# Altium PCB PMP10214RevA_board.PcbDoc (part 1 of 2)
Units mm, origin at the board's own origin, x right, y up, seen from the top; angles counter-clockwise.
Board outline 108.2 x 92.71 mm, 6 copper layers (Top Layer, MidLayer1, MidLayer2, MidLayer3, MidLayer4, Bottom Layer), stack 1.557 mm thick; 122 components, 44 nets, 289 pads, 1298 vias.
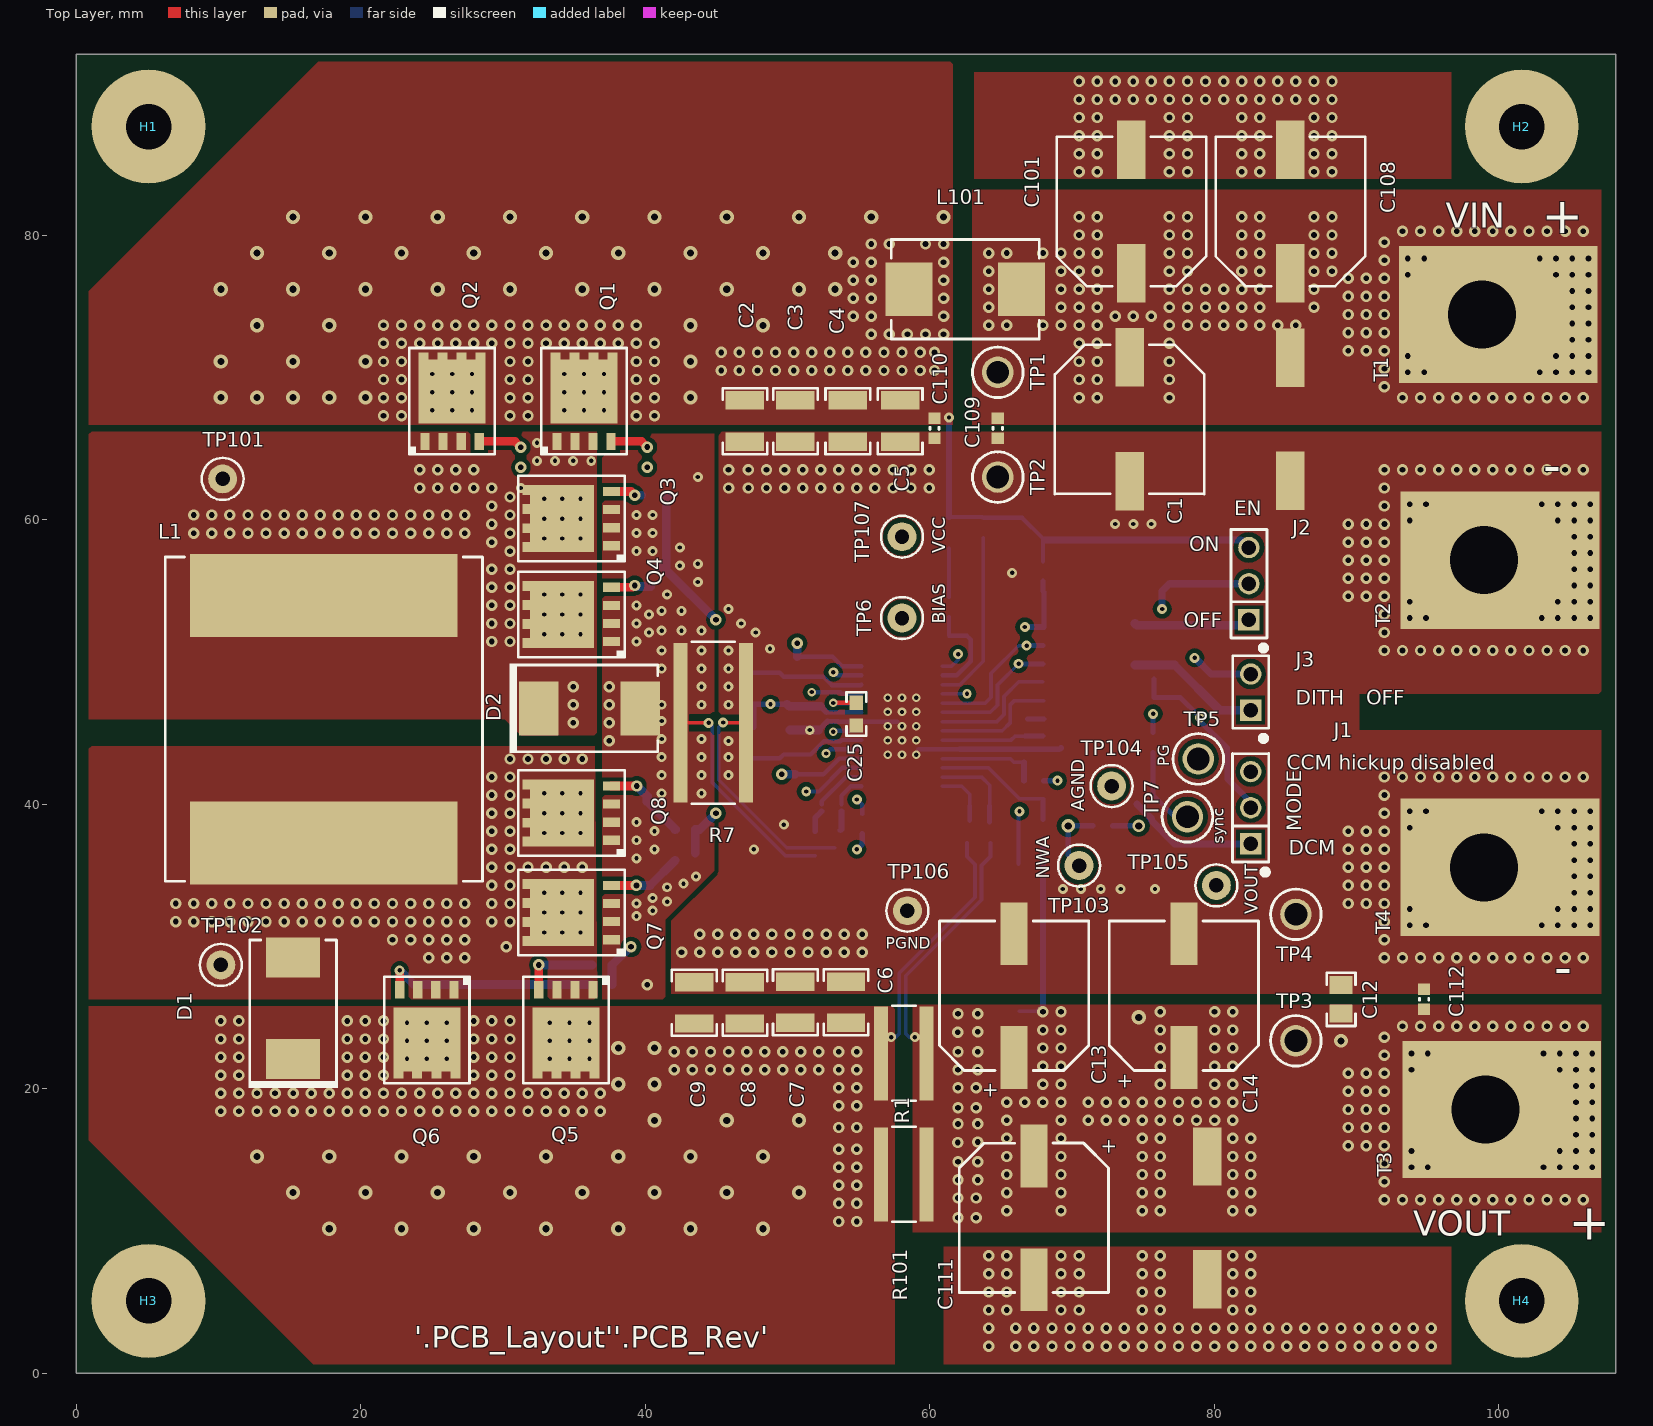
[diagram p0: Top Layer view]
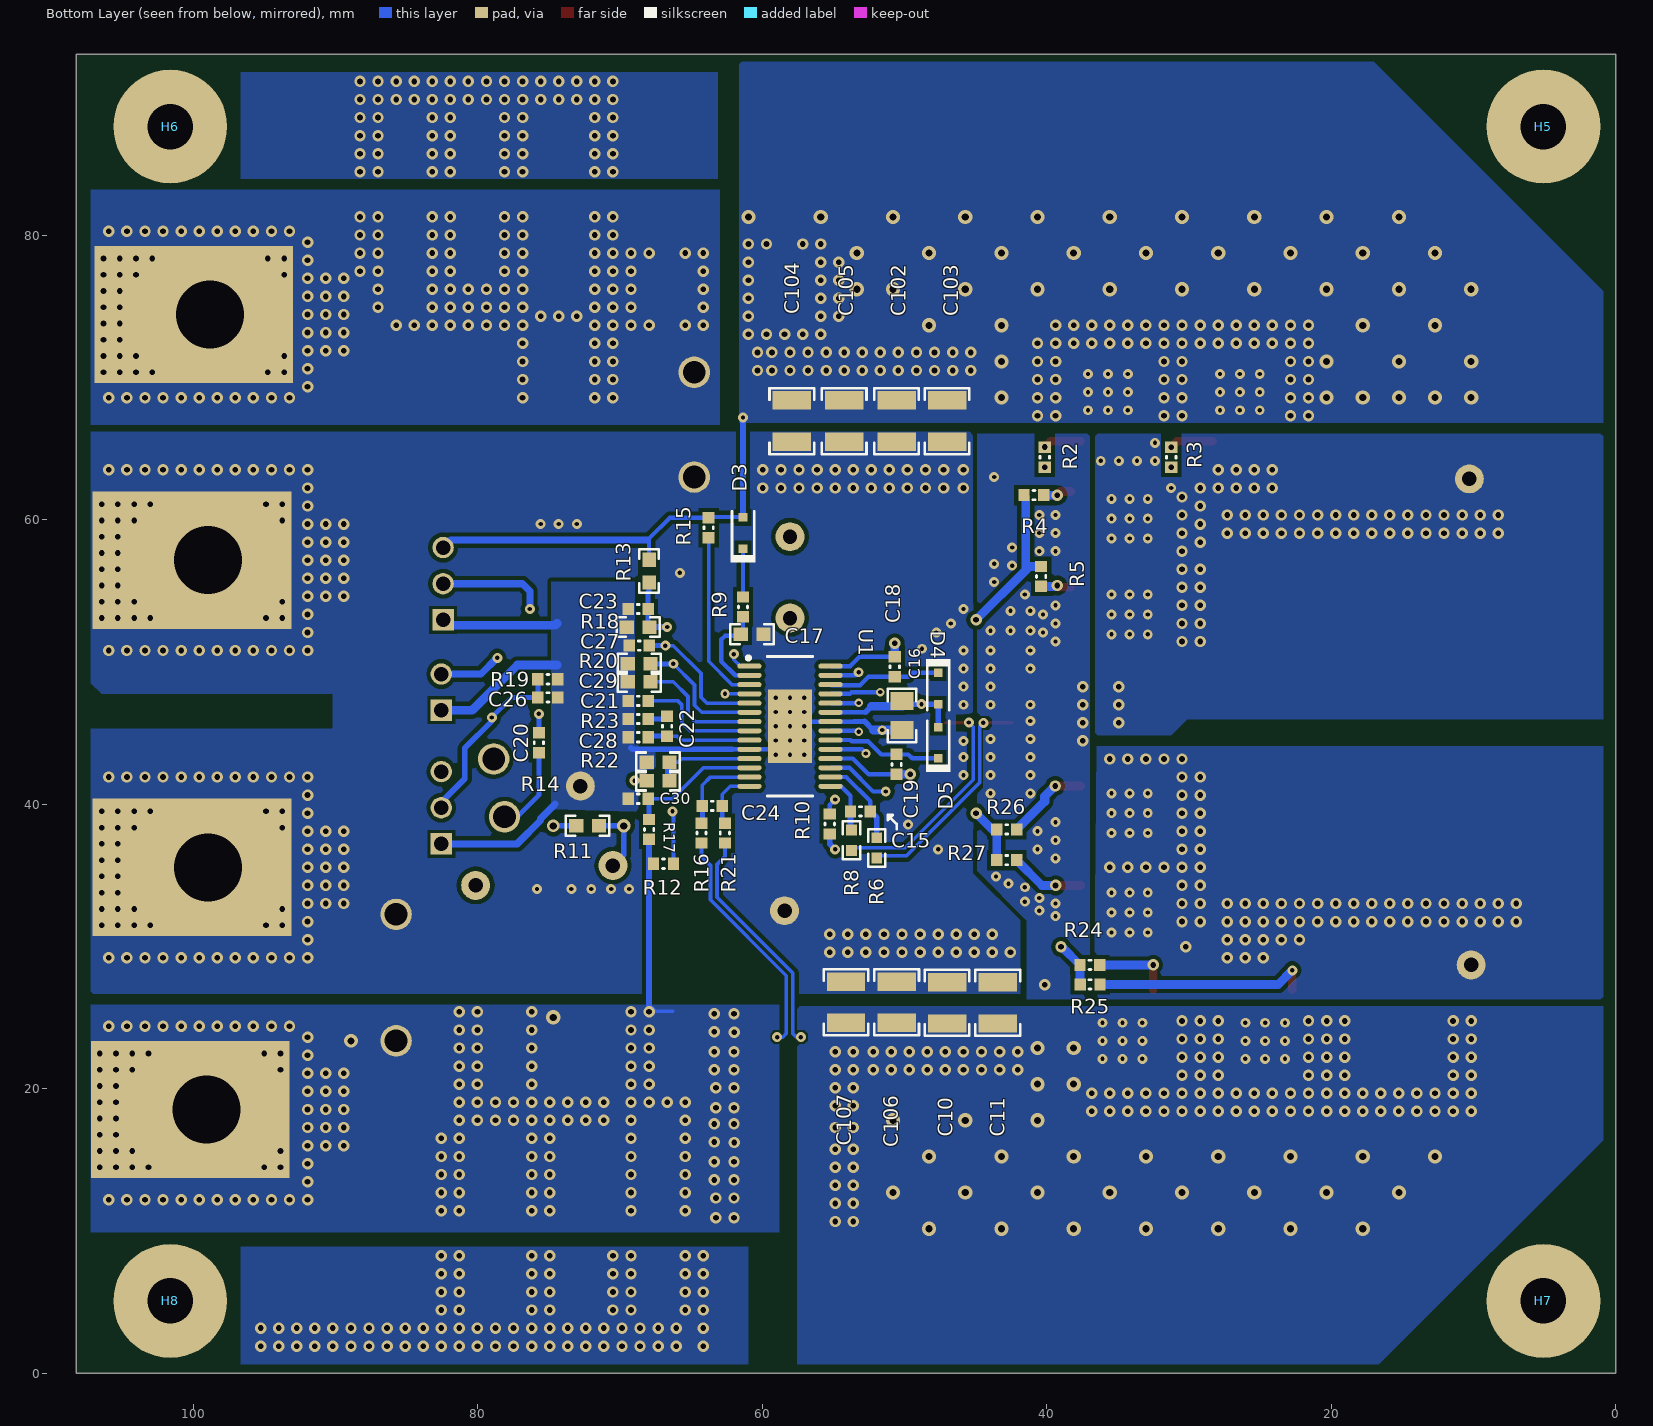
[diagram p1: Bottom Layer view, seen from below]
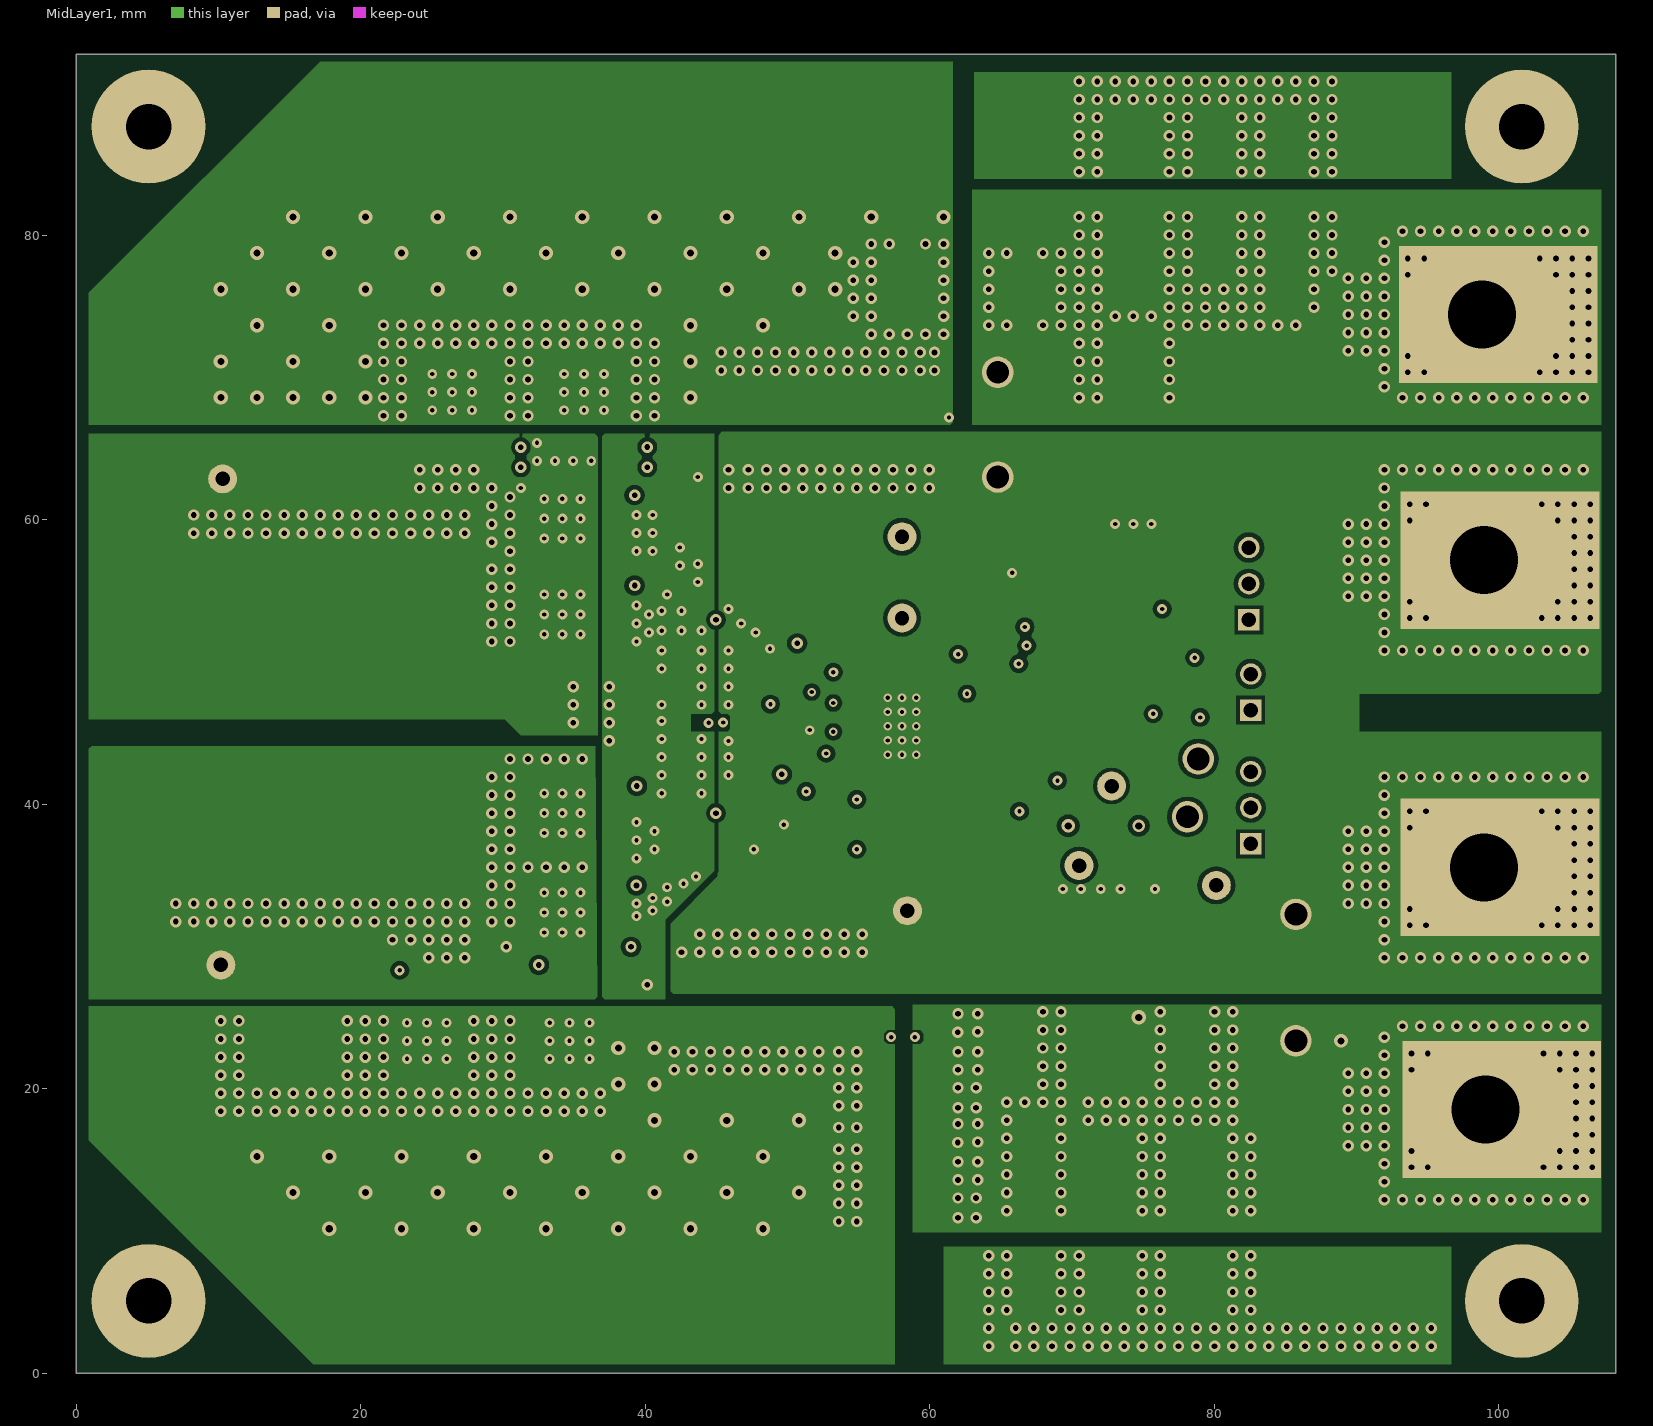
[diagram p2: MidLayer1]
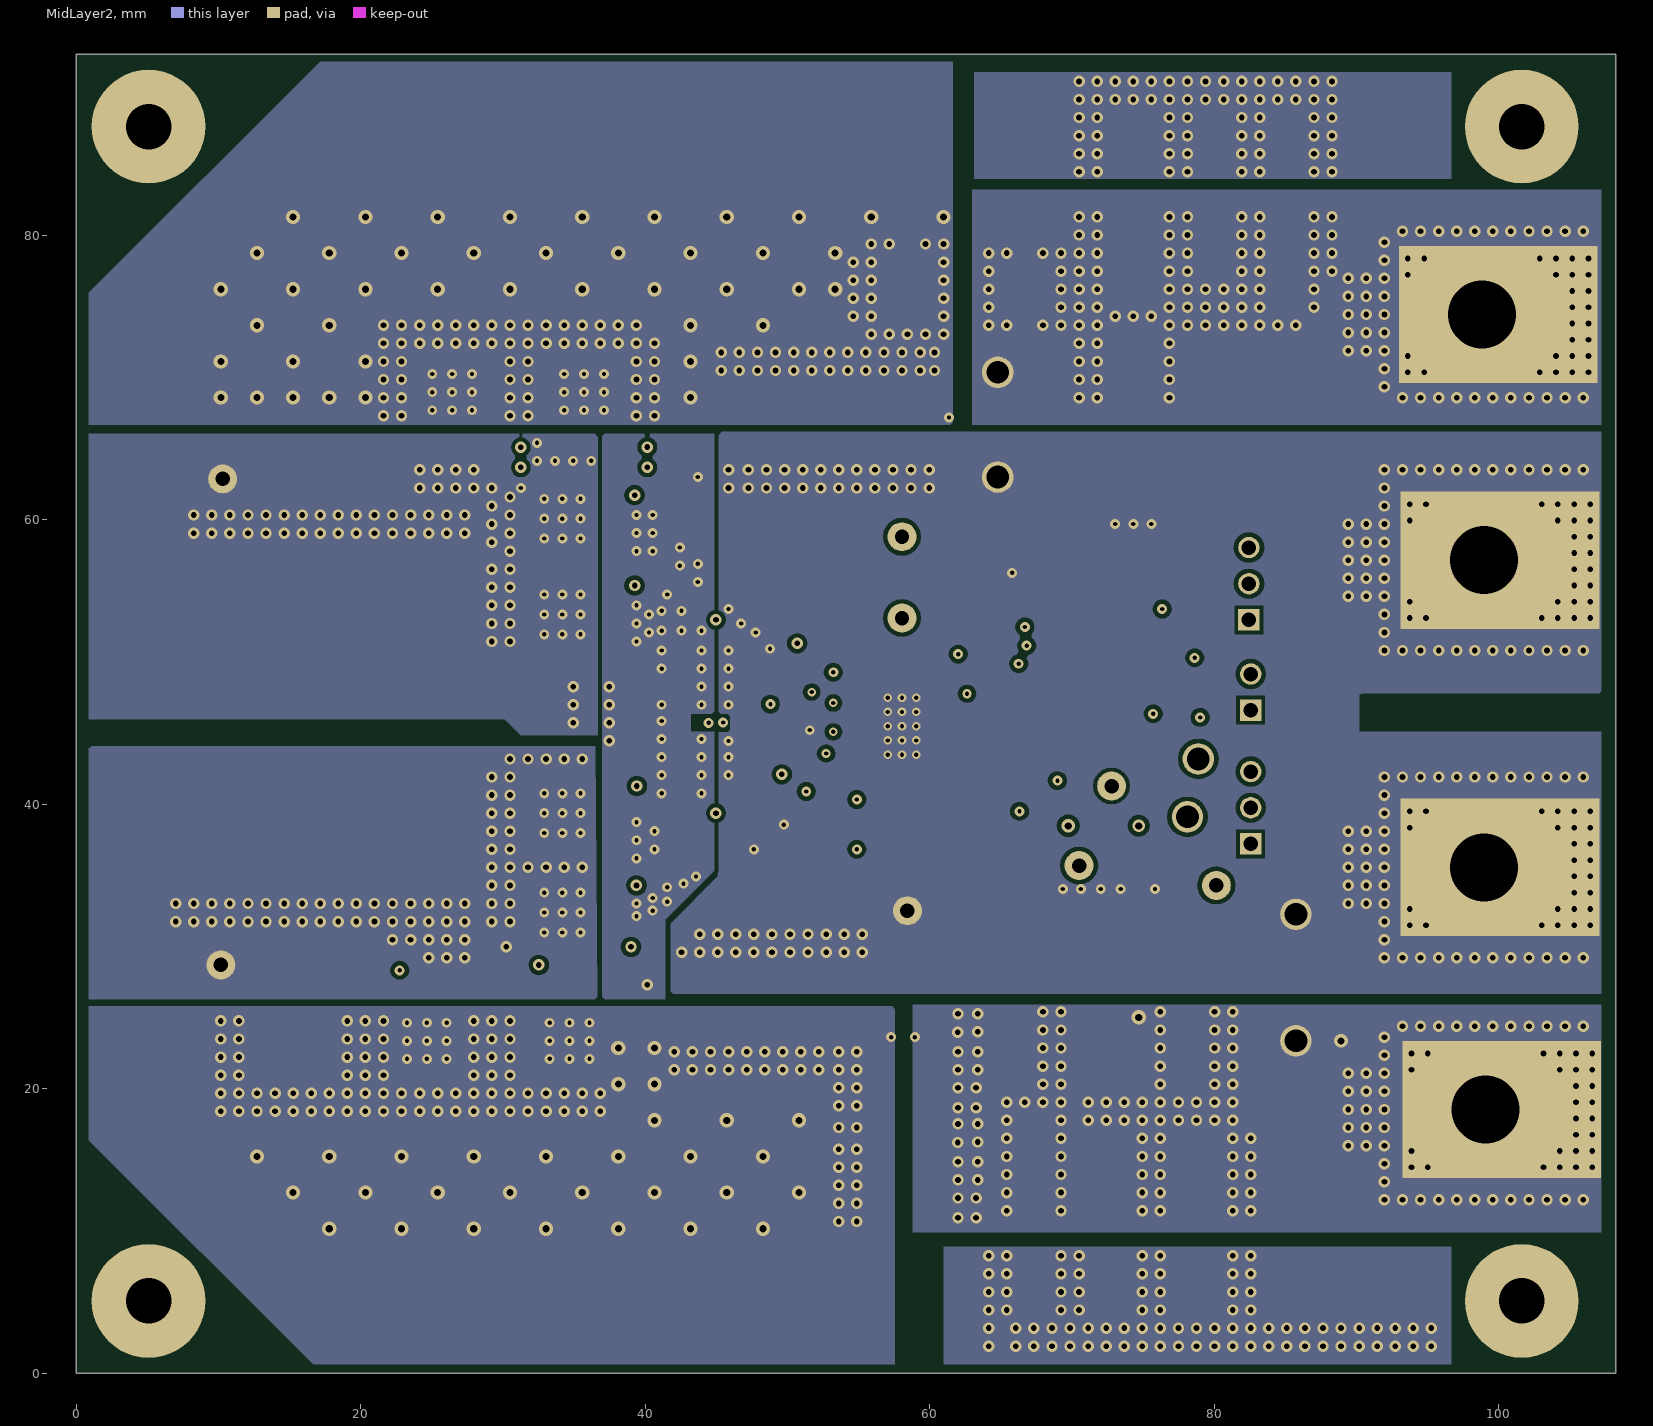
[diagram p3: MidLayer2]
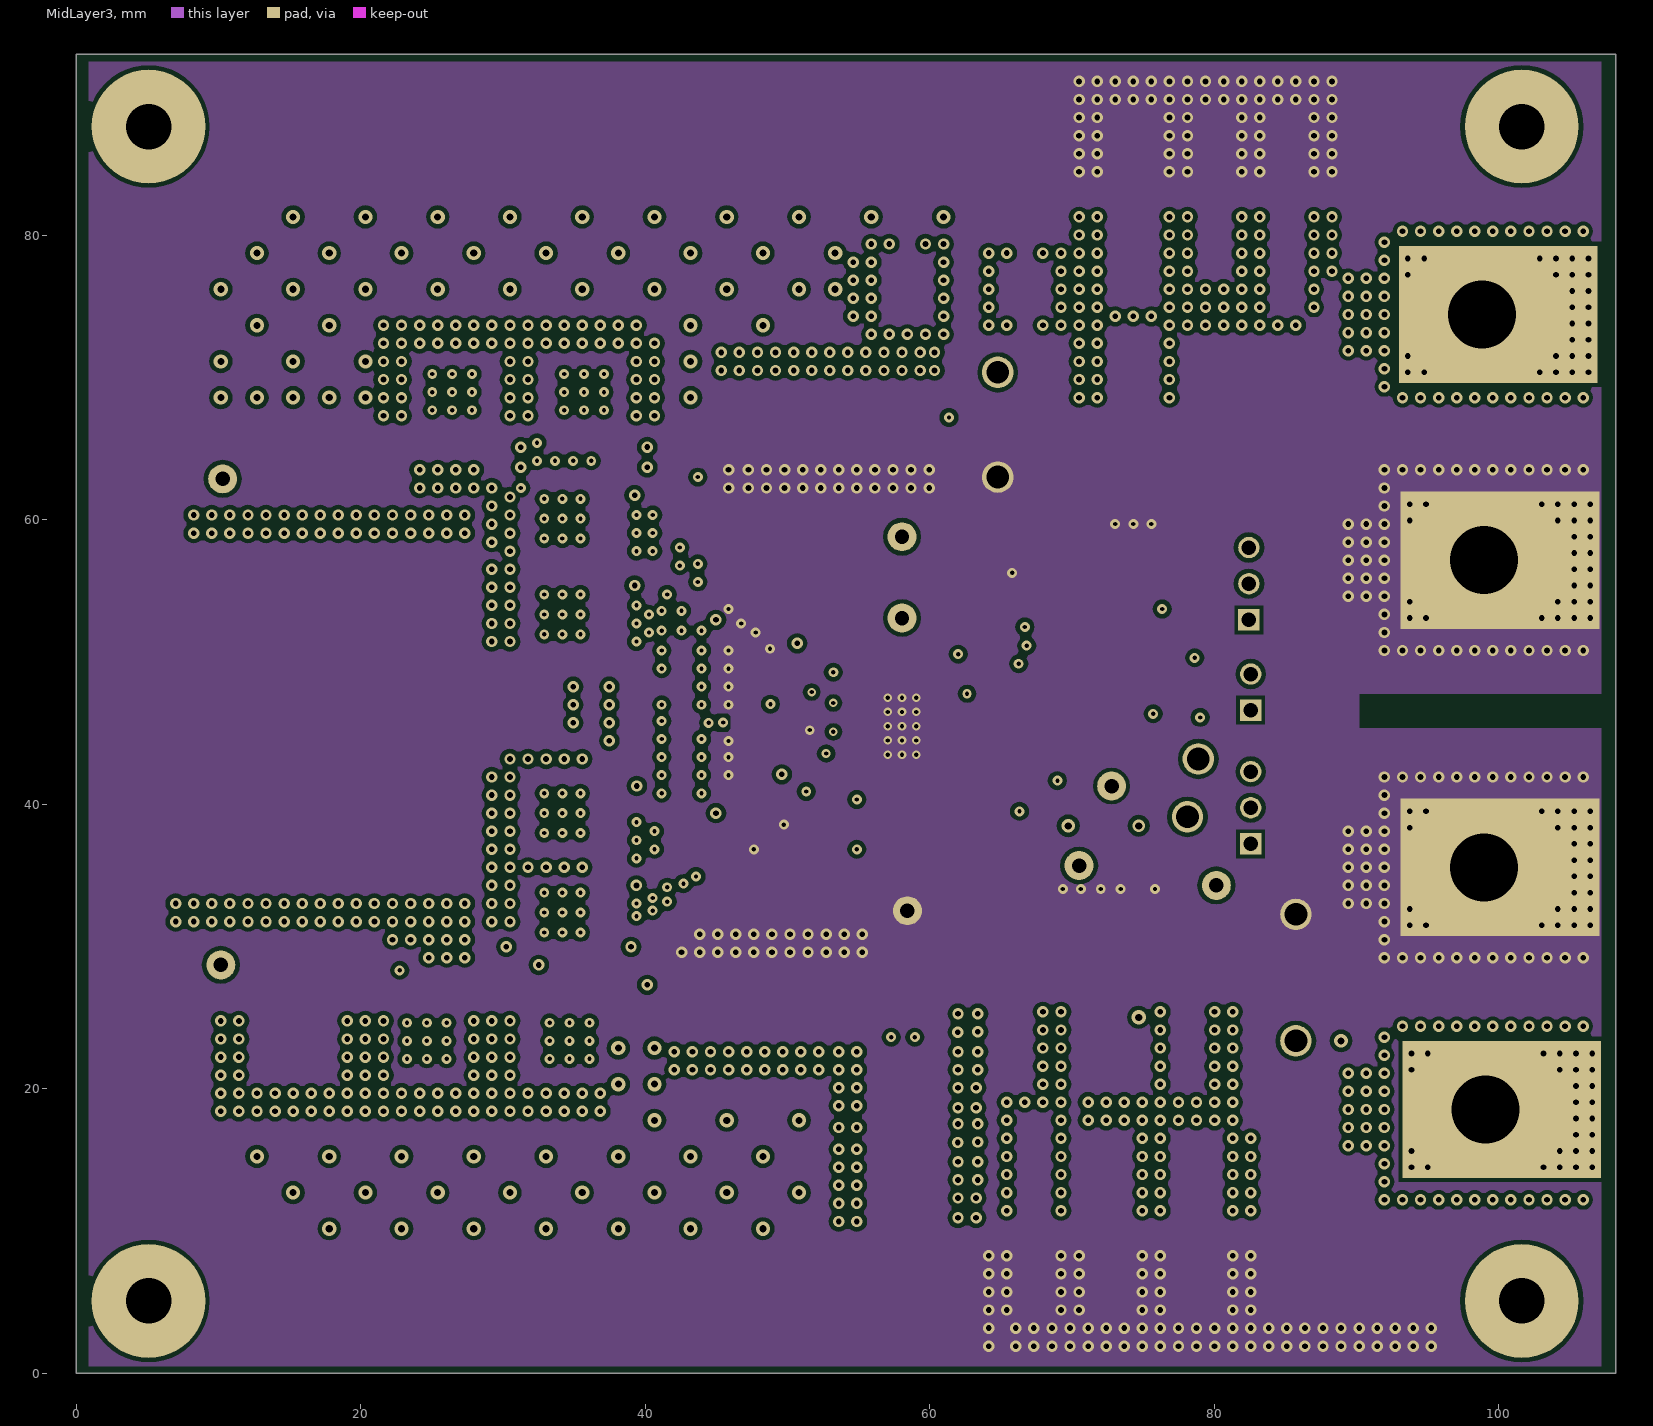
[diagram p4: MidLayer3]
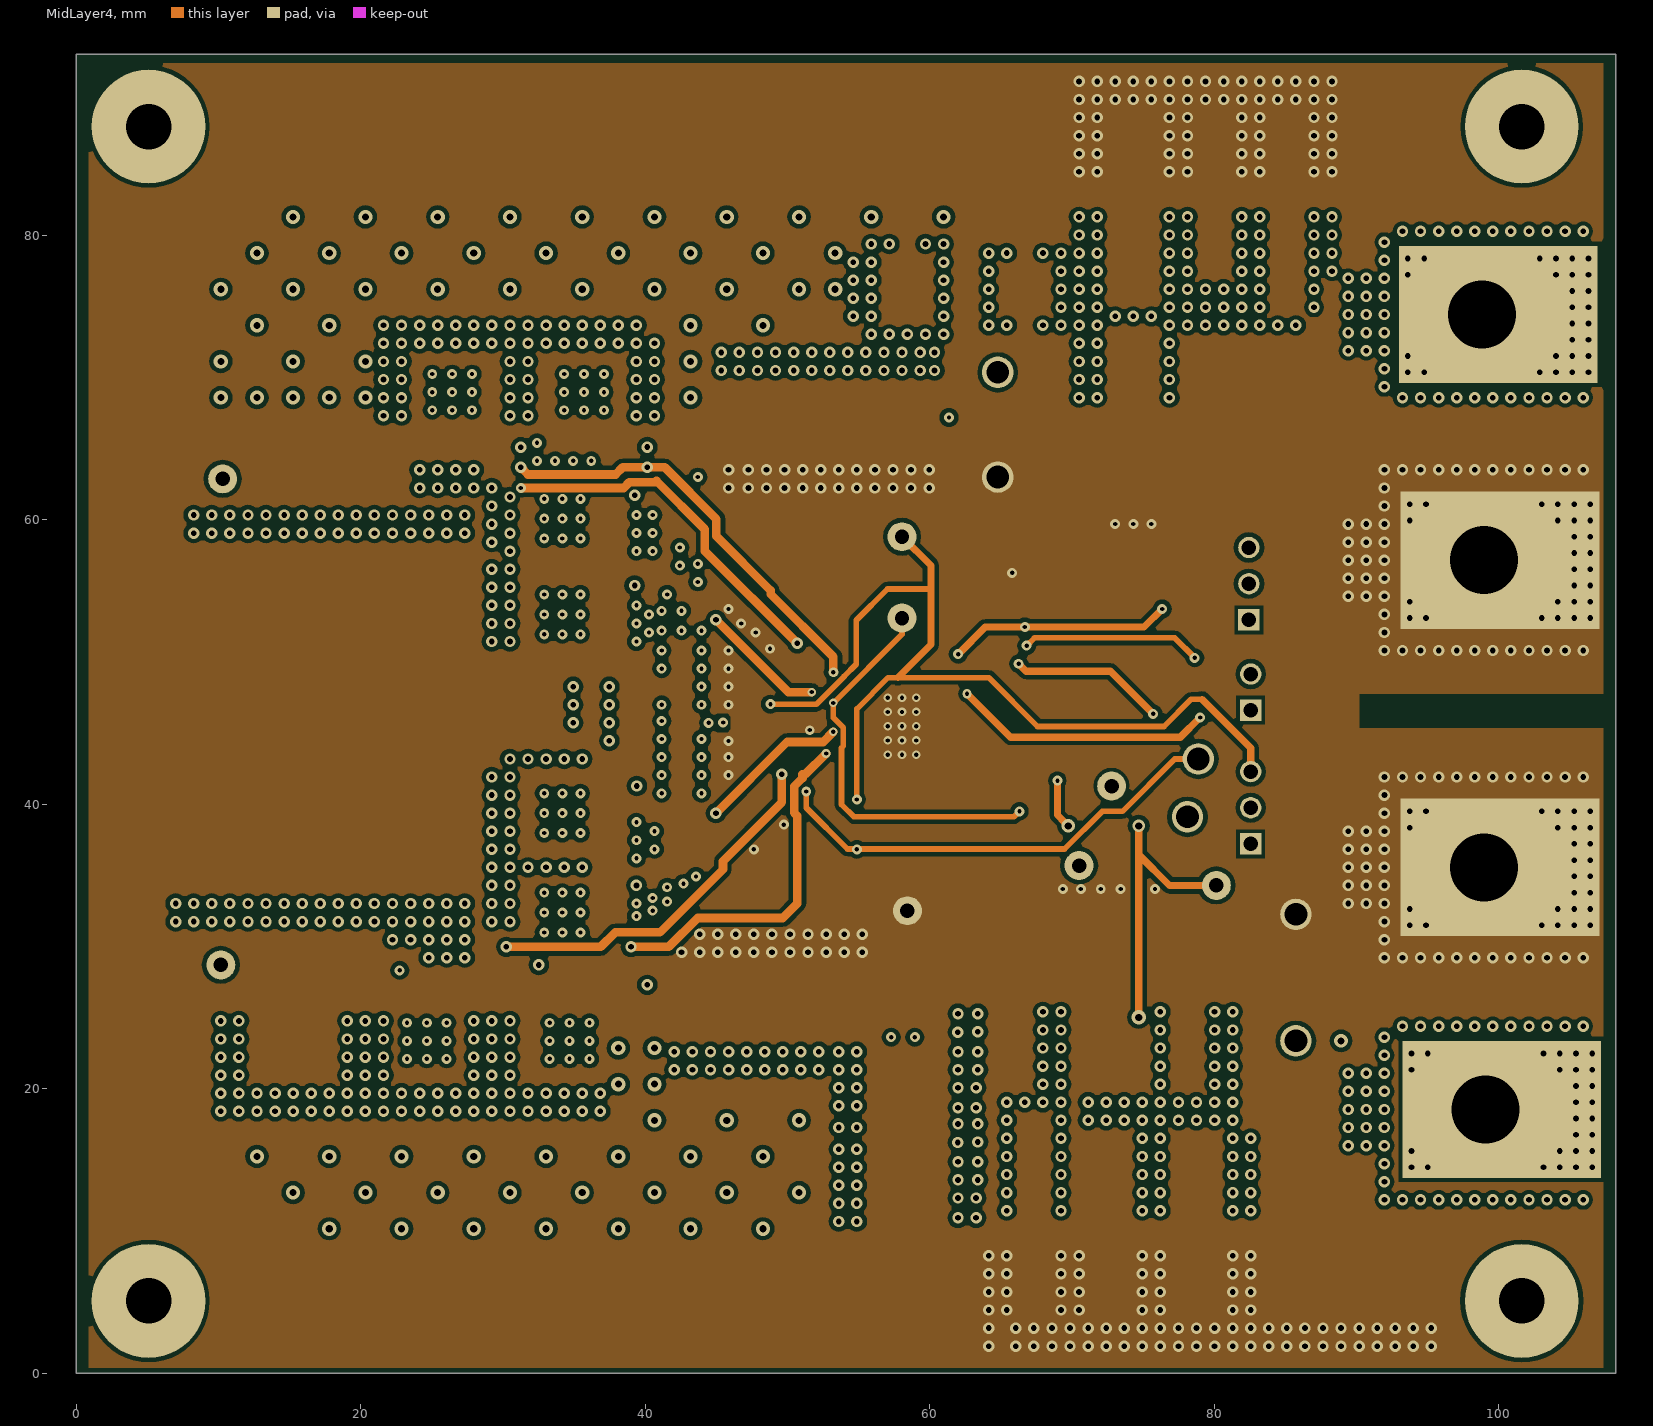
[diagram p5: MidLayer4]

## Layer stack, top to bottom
Top Solder: solder mask 0.0102, Solder Resist, Dk 3.5
Top Layer: signal copper 0.0711
Dielectric1: prepreg 0.2261, FR-4, Dk 4.2
MidLayer1: signal copper 0.0711
Dielectric3: prepreg 0.2261, FR-4, Dk 4.2
MidLayer2: signal copper 0.0711
Dielectric5: core 0.2261, FR-4, Dk 4.8
MidLayer3: signal copper 0.0711
Dielectric2: prepreg 0.2261, FR-4, Dk 4.8
MidLayer4: signal copper 0.0711
Dielectric4: prepreg 0.2261, FR-4, Dk 4.8
Bottom Layer: signal copper 0.0711
Bottom Solder: solder mask 0.0102, Solder Resist, Dk 3.5

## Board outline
0,0 0,92.71 108.204,92.71 108.204,0

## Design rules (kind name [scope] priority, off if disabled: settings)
AcuteAngle [All] p1: minimum=4.50000000000000E+0001 checktracksonly=FALSE
AssemblyTestPointUsage [All] p1: valid=2
Clearance Clearance_BoardEdge_MountingHoles [OnCopper and InComponentClass('Mounting Holes') vs KeepOut] p1: gap=1.016 ignorepadtopadclearanceinfootprint=FALSE except(0: Arc-Hole Track-Hole SMDPad-Hole THPad-Hole Via-Hole Fill-Hole Poly-Hole Region-Hole Text-Hole)
Clearance Clearance_BoardEdge_Poly [OnCopper and InPoly vs KeepOut] p2: gap=0.635 ignorepadtopadclearanceinfootprint=FALSE except(0: Arc-Hole Track-Hole SMDPad-Hole THPad-Hole Via-Hole Fill-Hole Poly-Hole Region-Hole Text-Hole)
Clearance Clearance_BoardEdge [OnCopper and Not InComponentClass('Logo') and not InComponentClass('FiducialMark') and not InRegion(1000,500,4000,800) and Not IsKeepout vs KeepOut] p3: gap=1.194 ignorepadtopadclearanceinfootprint=FALSE except(0: Arc-Hole Track-Hole SMDPad-Hole THPad-Hole Via-Hole Fill-Hole Poly-Hole Region-Hole Text-Hole)
Clearance Clearance_Poly [InPolygon] p4: gap=0.305 ignorepadtopadclearanceinfootprint=FALSE except(0: Arc-Hole Track-Hole SMDPad-Hole THPad-Hole Via-Hole Fill-Hole Poly-Hole Region-Hole Text-Hole)
Clearance [All] p5: gap=0.2 ignorepadtopadclearanceinfootprint=FALSE except(0: Arc-Hole Track-Hole SMDPad-Hole THPad-Hole Via-Hole Fill-Hole Poly-Hole Region-Hole Text-Hole)
ComponentClearance ComponentClearance_Shunt [InComponentClass('Header') vs InComponentClass('Shunt')] p1: gap=0 collisioncheckmode=3 verticalgap=0 showdistances=FALSE
ComponentClearance ComponentClearance_MountingHoles_FiducialMarks [InComponentClass('Mounting Holes') vs InComponentClass('FiducialMark')] p2: gap=1.067 collisioncheckmode=3 verticalgap=0.254 showdistances=FALSE
ComponentClearance ComponentClearance_Logo [InComponentClass('Logo')] p3: gap=1.27 collisioncheckmode=3 verticalgap=0.254 showdistances=FALSE
ComponentClearance ComponentClearance_ScrewToNut [(HasFootprint('NY PMS 440 0025 PH')) vs (HasFootprint('Keystone_1902C'))] p4: gap=0.127 collisioncheckmode=3 verticalgap=0.254 showdistances=FALSE
ComponentClearance ComponentClearance_MountingHoles [InComponentClass('Mounting Holes')] p5: gap=5.08 collisioncheckmode=3 verticalgap=2540 showdistances=FALSE
ComponentClearance ComponentClearance_SmallPassives [HasFootprint('0201*') or HasFootprint('0402*') or HasFootprint('0508') or HasFootprint('0603*') or HasFootprint('0612') or HasFootprint('0805*') or HasFootprint('0815*') or HasFootprint('0830*') or HasFootprint('1206*') or HasFootprint('1210*') or HasFootprint('1808*') or HasFootprint('1812*') or HasFootprint('1825*') or HasFootprint('2010*') or HasFootprint('2220*') or HasFootprint('2225*') or HasFootprint('2512*') or HasFootprint('2728*') or HasFootprint('3518*') vs HasFootprint('0201*') or HasFootprint('0402*') or HasFootprint('0508') or HasFootprint('0603*') or HasFootprint('0612') or HasFootprint('0805*') or HasFootprint('0815*') or HasFootprint('0830*') or HasFootprint('1206*') or HasFootprint('1210*') or HasFootprint('1808*') or HasFootprint('1812*') or HasFootprint('1825*') or HasFootprint('2010*') or HasFootprint('2220*') or HasFootprint('2225*') or HasFootprint('2512*') or HasFootprint('2728*') or HasFootprint('3518*')] p6: gap=0.254 collisioncheckmode=3 verticalgap=0.254 showdistances=FALSE
ComponentClearance ComponentClearance_THtoSMT [IsThruComponent vs IsSMTComponent] p7: gap=0.6 collisioncheckmode=3 verticalgap=0.762 showdistances=FALSE
ComponentClearance ComponentClearance_THtoTH [IsThruComponent vs IsThruComponent] p8: gap=0.635 collisioncheckmode=3 verticalgap=0.381 showdistances=FALSE
ComponentClearance [All] p9: gap=0.6 collisioncheckmode=3 verticalgap=0.254 showdistances=FALSE
DiffPairsRouting [All] p1: maxlimit=2.54 minlimit=0.254 mostfreqgap=0.254 toplayer_minwidth=0.381 toplayer_maxwidth=0.381 toplayer_prefwidth=0.381 midlayer1_minwidth=0.381 midlayer1_maxwidth=0.381 midlayer1_prefwidth=0.381 midlayer2_minwidth=0.381 midlayer2_maxwidth=0.381 midlayer2_prefwidth=0.381 midlayer3_minwidth=0.381 midlayer3_maxwidth=0.381 midlayer3_prefwidth=0.381 midlayer4_minwidth=0.381 midlayer4_maxwidth=0.381 midlayer4_prefwidth=0.381 bottomlayer_minwidth=0.381 bottomlayer_maxwidth=0.381 bottomlayer_prefwidth=0.381 maxuncoupledlength=25.4
FabricationTestPointUsage TestPointUsage [All] p1: valid=2 allowmultiple=FALSE
FabricationTestpoint Testpoint [All] p1: side=3 testpointundercomponent=TRUE minsize=1.016 maxsize=2.54 preferedsize=1.524 minholesize=0 maxholesize=1.016 preferedholesize=0.813 testpointgrid=0.025 allowsidetop=TRUE allowsidebottom=TRUE usegrid=TRUE gridtolerance=0
FanoutControl Fanout_LCC [IsLCC] p1: bgadir=Out bgaviamode=Centered fanoutstyle=Auto fanoutdirection=Alternating viagrid=0.025 // Fanout_LCC (Default Rule)
FanoutControl Fanout_BGA [IsBGA] p2: bgadir=Out bgaviamode=Centered fanoutstyle=Auto fanoutdirection=Alternating viagrid=0.025 // Fanout_BGA (Default Rule)
FanoutControl Fanout_Default [All] p4: bgadir=Out bgaviamode=Centered fanoutstyle=Auto fanoutdirection=Alternating viagrid=0.025 // Fanout_Default (Default Rule)
FanoutControl Fanout_Small [(CompPinCount < 5)] p5: bgadir=Out bgaviamode=Centered fanoutstyle=Auto fanoutdirection=OutThenIn viagrid=0.025 // Fanout_Small (Default Rule)
HoleSize [All] p1: absolutevalues=TRUE maxlimit=7.112 minlimit=0.3 maxpercent=80.000 minpercent=20.000
MinimumAnnularRing MinimumAnnularRing_ThermalPadVias [IsVia and InAnyComponent] p1: minimumring=0.1
MinimumAnnularRing [All] p2: minimumring=0.127
MinimumSolderMaskSliver MinimumSolderMaskSliver_Logo [InComponentClass('Logo') vs InComponentClass('Logo')] p1: minsoldermaskwidth=0.018
MinimumSolderMaskSliver [All] p2: minsoldermaskwidth=0.1
PlaneConnect [All] p1: planeconnectstyle=Relief reliefexpansion=0.254 reliefentries=4 reliefconductorwidth=0.254 reliefairgap=0.254
PolygonConnect [InComponent('J1') Or InComponent('J2') Or InComponent('J3')] p1: connectstyle=NoConnect reliefconductorwidth=0.254 reliefentries=4 polygonreliefangle="90 Angle" airgapwidth=0.254
PolygonConnect PolygonConnect_2 [OnLayer('Top Layer')Or OnLayer('MidLayer1') Or OnLayer('MidLayer2')Or OnLayer('MidLayer3')Or  OnLayer('MidLayer4') vs InComponent('TP104')] p2: connectstyle=NoConnect reliefconductorwidth=0.254 reliefentries=4 polygonreliefangle="90 Angle" airgapwidth=0.254
PolygonConnect PolygonConnect_1 [All] p3: connectstyle=Direct reliefconductorwidth=0.254 reliefentries=4 polygonreliefangle="90 Angle" airgapwidth=0.254
RoutingVias ThermalPadVias [IsVia and InAnyComponent] p1: holewidth=0.5 width=0.9 viastyle="Through Hole" minholewidth=0.3 minwidth=0.6 maxholewidth=1 maxwidth=2
RoutingVias [All] p2: holewidth=0.5 width=0.9 viastyle="Through Hole" minholewidth=0.3 minwidth=0.6 maxholewidth=1.016 maxwidth=1.651
SMDToCorner [All] p1: distance=30000
SilkToSilkClearance [All] p1: silktosilkclearance=0.127
SilkToSolderMaskClearance SilkscreenOverComponentPads [IsPad] p1: minsilkscreentomaskgap=0.127 clearancetoexposedcopper=TRUE
SolderMaskExpansion [All] p1: expansion=0.05 istentingtop=FALSE
Width [All] p1: maxlimit=2.54 minlimit=0.152 preferedwidth=0.254 checkconnectedcopper=TRUE
16 further rules are at their usual default settings.

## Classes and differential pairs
component class Header: J1 J2 J3
component class "Mounting Holes": H1 H2 H3 H4
component class PMP10214RevA-HW: H1 H2 H3 H4 H5 H6 H7 H8 ZZ2 ZZ3 ZZ4 ZZ5 ZZ6 ZZ7 ZZ8
component class AssemblyNote: ZZ2 ZZ3 ZZ4 ZZ5 ZZ6 ZZ7 ZZ8
component class PMP10214RevA: C1 C2 C3 C4 C5 C6 C7 C8 C9 C10 C11 C12 C13 C14 C15 C16 C17 C18 C19 C20 C21 C22 C23 C24 C25 C26 C27 C28 C29 C30 C101 C102 C103 C104 C105 C106 C107 C108 C109 C110 C111 C112 D1 D2 D3 D4 D5 J1 J2 J3 L1 L101 Q1 Q2 Q3 Q4 Q5 Q6 Q7 Q8 R1 R2 R3 R4 R5 R6 R7 R8 R9 R10 R11 R12 R13 R14 R15 R16 R17 R18 R19 R20 R21 R22 R23 R24 R25 R26 R27 R101 T1 T2 T3 T4 TP1 TP2 TP3 TP4 TP5 TP6 TP7 TP101 TP102 TP103 TP104 TP105 TP106 TP107 U1

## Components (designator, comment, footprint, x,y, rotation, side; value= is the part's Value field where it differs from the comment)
C1 "EEE-FK1H221P" SM_RADIAL_G 74.041,67.056 r270 top
C2 "GRM32ER71H106KA12L" 1210 46.99,66.929 r270 top
C3 "GRM32ER71H106KA12L" 1210 50.546,66.929 r270 top
C4 "GRM32ER71H106KA12L" 1210 54.229,66.929 r270 top
C5 "GRM32ER71H106KA12L" 1210 57.912,66.929 r270 top
C6 "GRM32ER71E226KE15L" 1210 54.102,26.084 r90 top
C7 "GRM32ER71E226KE15L" 1210 50.538,26.084 r90 top
C8 "GRM32ER71E226KE15L" 1210 46.99,26.035 r90 top
C9 "GRM32ER71E226KE15L" 1210 43.434,26.035 r90 top
C10 "GRM32ER71E226KE15L" 1210 46.99,26.035 r90 bottom
C11 "GRM32ER71E226KE15L" 1210 43.434,26.035 r90 bottom
C12 "GRM219R71E105KA88D" 0805_HV 88.9,26.289 r90 top
C13 "25SVPF330M" CAPSMT_62_F12 65.913,26.543 r90 top
C14 "25SVPF330M" CAPSMT_62_F12 77.851,26.543 r90 top
C15 "GRM1885C1H470JA01D" 0603L 53.086,39.497 r0 bottom
C16 "GRM21BR71C475KA73L" 0805_HV 50.165,46.228 r90 bottom
C17 "GRM188R61H105KAALD" 0603 60.706,51.943 r180 bottom
C18 "GRM188R71E224KA88D" 0603L 50.673,49.657 r270 bottom
C19 "GRM188R71E224KA88D" 0603L 50.546,42.799 r270 bottom
C20 "GRM1885C2A101JA01D" 0603L 75.692,44.323 r270 bottom
C21 "GRM188R72A104KA35D" 0603L 68.707,47.26 r0 bottom
C22 "GRM188R71E393KA01D" 0603L 66.675,45.482 r90 bottom
C23 "47pF" 0603L 68.707,53.721 r0 bottom
C24 "GRM188R71C334KA01D" 0603L 63.5,39.878 r0 bottom
C25 "GRM188R61H105KAALD" 0603 54.829,46.334 r270 top
C26 "47pF" 0603L 75.057,47.514 r180 bottom
C27 "C0603C223K5RACTU" 0603L 68.636,51.141 r0 bottom
C28 "GRM188R71H331KA01D" 0603L 68.707,44.704 r0 bottom
C29 "GRM1885C1H331JA01D" 0603 68.636,48.601 r0 bottom
C30 "GRM1885C2A101JA01D" 0603L 68.707,40.386 r0 bottom
C101 "EEE-FK1H221P" SM_RADIAL_G 74.168,81.661 r90 top
C102 "GRM32ER71H106KA12L" 1210 50.546,66.929 r270 bottom
C103 "GRM32ER71H106KA12L" 1210 46.99,66.929 r270 bottom
C104 "GRM32ER71H106KA12L" 1210 57.912,66.929 r270 bottom
C105 "GRM32ER71H106KA12L" 1210 54.229,66.929 r270 bottom
C106 "GRM32ER71E226KE15L" 1210 50.538,26.084 r90 bottom
C107 "GRM32ER71E226KE15L" 1210 54.102,26.084 r90 bottom
C108 "EEE-FK1H221P" SM_RADIAL_G 85.344,81.661 r90 top
C109 "GRM188R72A104KA35D" 0603L 64.77,66.421 r270 top
C110 "GRM188R72A104KA35D" 0603L 60.325,66.421 r270 top
C111 "25SVPF330M" CAPSMT_62_F12 67.31,10.922 r270 top
C112 "GRM188R72A104KA35D" 0603L 94.742,26.289 r90 top
D1 "B530C-13-F" SMC 15.24,25.654 r90 top
D2 "B560C-13-F" SMC 36.068,46.736 r0 top
D3 "PMEG6010CEJ,115" SOD-323F 61.341,59.055 r90 bottom
D4 "BAS316,115" sod-323 47.625,48.133 r270 bottom
D5 "BAS316,115" sod-323 47.625,44.323 r90 bottom
H1 "NY PMS 440 0025 PH" "NY PMS 440 0025 PH" 5.08,87.63 r0 top
H2 "NY PMS 440 0025 PH" "NY PMS 440 0025 PH" 101.6,87.63 r0 top
H3 "NY PMS 440 0025 PH" "NY PMS 440 0025 PH" 5.08,5.08 r0 top
H4 "NY PMS 440 0025 PH" "NY PMS 440 0025 PH" 101.6,5.08 r0 top
H5 "1902C" Keystone_1902C 5.08,87.63 r180 bottom
H6 "1902C" Keystone_1902C 101.6,87.63 r180 bottom
H7 "1902C" Keystone_1902C 5.08,5.08 r180 bottom
H8 "1902C" Keystone_1902C 101.6,5.08 r180 bottom
J1 "PEC03SAAN" CONN_PEC03SAAN 82.55,39.751 r90 top
J2 "PEC03SAAN" CONN_PEC03SAAN 82.423,55.499 r90 top
J3 "PEC02SAAN" CONN_PEC02SAAN 82.55,47.879 r90 top
L1 "IHLP8787MZER2R2M5A" IHLP8787MZ 17.399,45.974 r270 top
L101 "SLC1049-101MLB" SLC1049 62.484,76.2 r180 top
Q1 "BSC010N04LS" PG-TDSON-8 35.687,68.326 r90 top
Q2 "BSC010N04LS" PG-TDSON-8 26.416,68.326 r90 top
Q3 "BSC010N04LSI" PG-TDSON-8 34.798,60.071 r180 top
Q4 "BSC010N04LSI" PG-TDSON-8 34.798,53.34 r180 top
Q5 "BSC009NE2LS5I" PG-TDSON-8 34.417,24.13 r270 top
Q6 "BSC009NE2LS5I" PG-TDSON-8 24.638,24.13 r270 top
Q7 "BSC009NE2LS5" PG-TDSON-8 34.798,32.385 r180 top
Q8 "BSC009NE2LS5" PG-TDSON-8 34.798,39.37 r180 top
R1 "FCSL64R005FER" 2512_WIDE 58.166,22.479 r0 top
R2 "RC0603JR-070RL" 0603L 40.132,64.389 r270 bottom
R3 "RC0603JR-070RL" 0603L 31.242,64.389 r270 bottom
R4 "RC0603JR-070RL" 0603L 40.894,61.722 r0 bottom
R5 "RC0603JR-070RL" 0603L 40.386,56.007 r90 bottom
R6 "RC0603FR-07100RL" 0603_HV 51.943,36.932 r90 bottom
R7 "KRL11050-C-R002-G-T1" 4320 44.773,45.72 r180 top
R8 "RC0603FR-07100RL" 0603_HV 53.721,37.465 r90 bottom
R9 "RC0603FR-0710RL" 0603L 61.341,53.864 r90 bottom
R10 "RC0603FR-0710KL" 0603L 55.245,38.608 r90 bottom
R11 "CRCW060349R9FKEA" 0603 72.263,38.481 r0 bottom
R12 "RC0603JR-070RL" 0603L 66.929,35.814 r0 bottom
R13 "CRCW0603499KFKEA" 0603 67.945,56.388 r90 bottom
R14 "CRCW0603100KFKEA" 0603 67.31,41.656 r0 bottom
R15 "RC0603JR-070RL" 0603L 63.754,59.436 r90 bottom
R16 "100" 0603L 64.262,37.973 r90 bottom
R17 "RC0603JR-070RL" 0603L 67.945,38.227 r90 bottom
R18 "CRCW060364K9FKEA" 0603 68.707,52.451 r180 bottom
R19 "RC0603FR-0793K1L" 0603L 75.057,48.784 r0 bottom
R20 "CRCW0603118KFKEA" 0603 68.636,49.871 r180 bottom
R21 "100" 0603L 62.611,37.973 r90 bottom
R22 "CRCW06034K99FKEA" 0603 67.309,42.942 r180 bottom
R23 "CRCW060310K0FKEA" 0603L 68.707,45.99 r180 bottom
R24 "RC0603JR-070RL" 0603L 36.957,28.702 r0 bottom
R25 "RC0603JR-070RL" 0603L 36.948,27.33 r0 bottom
R26 "RC0603JR-070RL" 0603L 42.799,36.068 r0 bottom
R27 "RC0603JR-070RL" 0603L 42.799,38.227 r0 bottom
R101 "FCSL64R005FER" 2512_WIDE 58.166,13.97 r0 top
T1 "CB35-36-CY" CB35-36-CY 98.806,74.422 r180 top
T2 "CB35-36-CY" CB35-36-CY 98.933,57.15 r180 top
T3 "CB35-36-CY" CB35-36-CY 99.06,18.542 r180 top
T4 "CB35-36-CY" CB35-36-CY 98.933,35.56 r180 top
TP1 "5005" Keystone5005 64.77,70.358 r90 top
TP2 "5006" Keystone5006 64.77,62.992 r90 top
TP3 "5005" Keystone5005 85.725,23.368 r90 top
TP4 "5006" Keystone5006 85.725,32.258 r90 top
TP5 "5007" Keystone5007 78.867,43.18 r90 top
TP6 "5000" Keystone5000 58.039,53.086 r90 top
TP7 "SYNC" Keystone5007 78.105,39.116 r90 top
TP101 "5002" Keystone5002 10.287,62.865 r0 top
TP102 "5002" Keystone5002 10.16,28.702 r0 top
TP103 "5003" Keystone5003 70.485,35.687 r0 top
TP104 "5001" Keystone5001 72.771,41.275 r0 top
TP105 "5000" Keystone5000 80.137,34.29 r0 top
TP106 "5001" Keystone5001 58.42,32.512 r0 top
TP107 "5000" Keystone5000 58.039,58.801 r0 top
U1 "LM5175PWPR" PWP0028F_N 58.039,45.482 r180 bottom
ZZ2 "These assemblies are ESD sensitive, ESD precautions shall be observed." AssemblyNote 2.667,112.976 r0 top
ZZ3 "These assemblies must be clean and free from flux and all contaminants. Use of no clean flux is not acceptable." AssemblyNote 2.667,110.821 r0 top
ZZ4 "These assemblies must comply with workmanship standards IPC-A-610 Class 2, unless otherwise specified." AssemblyNote 2.667,108.667 r0 top
ZZ5 "Remove Kapton tape from switches S1 thru S3 on PCB Bottom side after final wash." AssemblyNote 2.667,106.513 r0 top
ZZ6 "Set S1 switch to 'CCM' position as per silkscreen label" AssemblyNote 2.667,104.359 r0 top
ZZ7 "Set S2 switch to Center position" AssemblyNote 2.667,102.205 r0 top
ZZ8 "Set S3 switch to 'OFF' position per silk screen label." AssemblyNote 2.667,100.051 r0 top

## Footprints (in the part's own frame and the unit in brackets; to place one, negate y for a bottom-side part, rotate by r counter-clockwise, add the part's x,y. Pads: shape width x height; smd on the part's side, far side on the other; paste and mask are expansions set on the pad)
0603 [mm] "0603 from SM-752 data"
  rect 1x0.95 smd: 1(-0.8,0) 2(0.8,0)
  silkscreen extent -1.52,-0.69 1.52,0.69, body extent -0.87,-0.47 0.87,0.47, height 1
0603_HV [mil] "Ernesto recommended land pattern.  26 mil between pads."
  rect 30x30 smd: 1(-28,0) 2(28,0)
  silkscreen extent -52,-24 52,24, body extent -34,-19 34,19, height 33
0603L [mm] "0603 from SM-752 data"
  rect 0.8x0.85 smd: 1(-0.7,0) 2(0.7,0)
  silkscreen extent -0.07,-0.33 0.07,0.33, body extent -0.87,-0.47 0.87,0.47, height 0.85
0805_HV [mil] "0805 with 30mil clearance between pads"
  rect 50x63 smd: 1(-40,0) 2(40,0)
  silkscreen extent -74,-40 74,40, body extent -43,-29 43,29, height 43
1210 [mm] "1210 from SM-752 data"
  rect 1.3x2.7 smd: 1(-1.45,0) 2(1.45,0)
  silkscreen extent -2.32,-1.57 2.32,1.57, body extent -1.7,-1.35 1.7,1.35, height 1.35
2512_WIDE [mm] "Ohmite recommended land pattern"
  rect 1x6.6 smd: 1(-1.6,0) 2(1.6,0)
  silkscreen extent -0.82,-3.32 0.82,3.35, body extent -1.65,-3.25 1.65,3.25, height 0.7
4320 [mm] "SUSUMU"
  rect 1x11.2 smd: 1(-2.3,0) 2(2.3,0)
  silkscreen extent -1.5,-5.7 1.5,5.7, body extent -2.6,-5.6 2.6,5.6, height 0.7
AssemblyNote [mm] "Assembly Note"
CAPSMT_62_F12 [mm] "F12, SMD, 2-Leads, Body 10.5x10.5mm, Height 12.7mm"
  rect 4.4x1.9 smd: 1(-4.35,0) 2(4.35,0)
  silkscreen extent -5.25,-5.25 5.25,5.25, body extent -5.25,-5.25 5.25,5.25, height 12.71
CB35-36-CY [mil] "Terminal 50A Lug"
  rect 550x380 hole 188 copper offset -45,0 paste-190: 1(0,0)
  body extent -960,-189 230,191, height 614
CONN_PEC02SAAN [mm] "SULLINS"
  rect 1.5x1.5 hole 1.016: 1(-1.27,0)
  round 1.5 hole 1.016: 2(1.27,0)
  silkscreen extent -3.45,-1.27 2.54,1.27, body extent -2.54,-1.27 2.54,1.27, height 8.38
CONN_PEC03SAAN [mm] "SULLINS"
  rect 1.5x1.5 hole 1.016: 1(-2.54,0)
  round 1.5 hole 1.016: 2(0,0) 3(2.54,0)
  silkscreen extent -4.72,-1.27 3.81,1.27, body extent -3.84,-1.3 3.84,1.3, height 8.38
IHLP8787MZ [mm] "SMD, 2-Leads, Body 22x22.48mm"
  rect 5.84x18.8 smd: 1(-8.7,0) 2(8.7,0)
  silkscreen extent -11.39,-11.15 11.39,11.15, body extent -11.39,-11.15 11.39,11.15, height 13
Keystone5000 [mil] "For Keystone 500x miniature loop terminals"
  round 80 hole 40: 1(0,0)
  silkscreen extent -58,-58 58,58, body extent -49,-49 49,49, height 182
Keystone5001 [mil] "For Keystone 500x miniature loop terminals"
  round 80 hole 40: 1(0,0)
  silkscreen extent -58,-58 58,58, body extent -49,-49 49,49, height 182
Keystone5002 [mil] "For Keystone 500x miniature loop terminals"
  round 80 hole 40: 1(0,0)
  silkscreen extent -58,-58 58,58, body extent -49,-49 49,49, height 182
Keystone5003 [mil] "For Keystone 500x miniature loop terminals"
  round 80 hole 40: 1(0,0)
  silkscreen extent -58,-58 58,58, body extent -49,-49 49,49, height 182
Keystone5005 [mil] "Keystone Compact loops"
  round 87 hole 63: 1(0,0)
  silkscreen extent -70,-70 70,70, body extent -63,-63 62,63, height 225
Keystone5006 [mil] "Keystone Compact loops"
  round 87 hole 63: 1(0,0)
  silkscreen extent -70,-70 70,70, body extent -63,-63 62,63, height 225
Keystone5007 [mil] "Keystone Compact loops"
  round 87 hole 63: 1(0,0)
  silkscreen extent -70,-70 70,70, body extent -63,-63 62,63, height 225
Keystone_1902C [mm] "Hex Standoff, 4-40 threaded, nylon"
  body extent -3.68,-3.2 3.71,3.2, height 12.73
"NY PMS 440 0025 PH" [mm] "4-40 nylon screw and mounting hole"
  round 8 hole 3.2 mask+0.05: 1(0,0)
  body extent -3.3,-3.3 3.3,3.3, height 2.69
PG-TDSON-8 [mm] "Infineon recommended land pattern"
  rect 1.2x0.65 smd: 1(-2.825,1.905) 2(-2.825,0.635) 3(-2.825,-0.635) 4(-2.825,-1.905)
  rect 0.5x0.7 smd: 5(3.175,-2) 6(3.175,-0.675) 7(3.175,0.675) 8(3.175,2)
  rect 4.5x4.7 smd paste-2.25: 9(0.675,0)
  silkscreen extent -3.74,-3 3.74,3, body extent -3.17,-2.89 3.17,2.9, height 1.1
PWP0028F_N [mm] "TSOP, 28-Leads, Body 9.7x4.4mm, Pitch 0.65mm, Exposed Pad, IPC Medium Density"
  oval 1.7x0.35 smd: 1(-2.85,4.225) 2(-2.85,3.575) 3(-2.85,2.925) 4(-2.85,2.275) 5(-2.85,1.625) 6(-2.85,0.975) 7(-2.85,0.325) 8(-2.85,-0.325) 9(-2.85,-0.975) 10(-2.85,-1.625) 11(-2.85,-2.275) 12(-2.85,-2.925) 13(-2.85,-3.575) 14(-2.85,-4.225) 15(2.85,-4.225) 16(2.85,-3.575) 17(2.85,-2.925) 18(2.85,-2.275) 19(2.85,-1.625) 20(2.85,-0.975) 21(2.85,-0.325) 22(2.85,0.325) 23(2.85,0.975) 24(2.85,1.625) 25(2.85,2.275) 26(2.85,2.925) 27(2.85,3.575) 28(2.85,4.225)
  rect 3.1x5.18 smd: 29(0,0)
  silkscreen extent -3.05,-4.9 1.6,4.92, body extent -3.21,-4.85 3.21,4.85, height 0.98
SLC1049 [mm] "COILCRAFT"
  rect 3.3x3.76 smd: 1(-3.95,0) 2(3.95,0)
  silkscreen extent -5.2,-3.5 5.2,3.5, body extent -5.1,-3.44 5.1,3.44, height 5.16
SM_RADIAL_G [mm] "10 x 10.2mm:  Panasonic G"
  rect 4.1x2 smd: 1(-4.35,0) 2(4.35,0)
  silkscreen extent -5.25,-5.25 5.25,5.25, body extent -5.25,-5.25 5.25,5.25, height 10.5
SMC [mil] "Molded Diode, 2-Leads, Body 6.9x5.8mm, IPC Medium Density, based on OnSemi component dimensions and land patterns"
  rect 110x150 smd: 1(-140.49,0) 2(140.49,0)
  silkscreen extent -221,-124 189,123, body extent -156,-116 156,116, height 91
sod-323 [mm] "NXP recommended land pattern"
  rect 0.6x0.6 smd paste-0.05: 1(-1.1,0) 2(1.1,0)
  silkscreen extent -2.06,-0.86 1.53,0.86, body extent -1.3,-0.67 1.3,0.68, height 1.1
SOD-323F [mm] "NXP recommended land pattern"
  rect 0.6x0.6 smd paste-0.05: 1(-1.1,0) 2(1.1,0)
  silkscreen extent -2.06,-0.86 1.53,0.86, body extent -1.35,-0.67 1.35,0.67, height 0.79

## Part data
C1 C101 C108: "CAP, AL, 220 µF, 50 V, +/- 20%, 0.18 ohm, SMD"
C2 C3 C4 C5 C102 C103 C104 C105: "CAP, CERM, 10 µF, 50 V, +/- 10%, X7R, 1210"
C6 C7 C8 C9 C10 C11 C106 C107: "CAP, CERM, 22 µF, 25 V, +/- 10%, X7R, 1210"
C12: "CAP, CERM, 1 µF, 25 V, +/- 10%, X7R, 0805"
C13 C14 C111: "CAP, Polymer, 330 µF, 25 V, +/- 20%, 0.014 ohm, F12, SMD, 2-Leads, Body 10.5x10.5mm, Height 12.7mm SMD"
C15: "CAP, CERM, 47pF, 50V, +/-5%, C0G/NP0, 0603"
C16: "CAP, CERM, 4.7 µF, 16 V, +/- 10%, X7R, 0805"
C17 C25: "CAP, CERM, 1 µF, 50 V, +/- 10%, X5R, 0603"
C18 C19: "CAP, CERM, 0.22 µF, 25 V, +/- 10%, X7R, 0603"
C20 C30: "CAP, CERM, 100pF, 100V, +/-5%, C0G/NP0, 0603"
C21 C109 C110 C112: "CAP, CERM, 0.1uF, 100V, +/-10%, X7R, 0603"
C22: "CAP, CERM, 0.039 µF, 25 V, +/- 10%, X7R, 0603"
C23 C26: library part GRM1885C1H470JA01D, "CAP, CERM, 47pF, 50V, +/-5%, C0G/NP0, 0603"
C24: "CAP, CERM, 0.33 µF, 16 V, +/- 10%, X7R, 0603"
C27: "CAP, CERM, 0.022uF, 50V, +/-10%, X7R, 0603"
C28: "CAP, CERM, 330 pF, 50 V, +/- 10%, X7R, 0603"
C29: "CAP, CERM, 330 pF, 50 V, +/- 5%, C0G/NP0, 0603"
D1: "Diode, Schottky, 30 V, 5 A, SMC"
D2: "Diode, Schottky, 60 V, 5 A, SMC"
D3: "Diode, Schottky, 60 V, 1 A, SOD-323F"
D4 D5: "Diode, Ultrafast, 100V, 0.25A, SOD-323"
H1 H2 H3 H4: "Machine Screw, Round, #4-40 x 1/4, Nylon, Philips panhead"
H5 H6 H7 H8: "Standoff, Hex, 0.5\"L #4-40 Nylon"
J1 J2: "Header, 100mil, 3x1, Tin, TH"
J3: "Header, 100mil, 2x1, Tin, TH"
L1: "Inductor, Shielded, 2.2 µH, 48 A, 0.00123 ohm, SMD"
L101: "Inductor, Shielded, Ferrite, 100 nH, 43 A, 0.000273 ohm, SMD"
Q1 Q2 Q3 Q4: library part "BSC016N04LS G", "MOSFET, N-CH, 40 V, 100 A, PG-TDSON-8"
Q5 Q6 Q7 Q8: library part BSC009NE2LS, "MOSFET, N-CH, 25 V, 100 A, PG-TDSON-8"
R1 R101: "RES, 0.005, 1%, 2 W, 2512 WIDE"
R2 R3 R4 R5 R12 R15 R17 R24 R25 R26 R27: "RES, 0 ohm, 5%, 0.1W, 0603"
R6 R8: "RES, 100 ohm, 1%, 0.1W, 0603"
R7: "RES, 0.002, 2%, 6 W, 4320_WIDE"
R9: "RES, 10.0 ohm, 1%, 0.1W, 0603"
R10: "RES, 10.0k ohm, 1%, 0.1W, 0603"
R11: "RES, 49.9, 1%, 0.1 W, 0603"
R13: "RES, 499 k, 1%, 0.1 W, 0603"
R14: "RES, 100 k, 1%, 0.1 W, 0603"
R16 R21: library part RC0603FR-07100RL, "RES, 100 ohm, 1%, 0.1W, 0603"
R18: "RES, 64.9 k, 1%, 0.1 W, 0603"
R19: "RES, 93.1 k, 1%, 0.1 W, 0603"
R20: "RES, 118 k, 1%, 0.1 W, 0603"
R22: "RES, 4.99 k, 1%, 0.1 W, 0603"
R23: "RES, 10.0 k, 1%, 0.1 W, 0603"
T1 T2 T3 T4: "Terminal 50A Lug"
TP1 TP3: "Test Point, Compact, Red, TH"
TP2 TP4: "Test Point, Compact, Black, TH"
TP5: "Test Point, Compact, White, TH"
TP6 TP105 TP107: "Test Point, Miniature, Red, TH"
TP7: library part 5007, "Test Point, Compact, White, TH"
TP101 TP102: "Test Point, Miniature, White, TH"
TP103: "Test Point, Miniature, Orange, TH"
TP104 TP106: "Test Point, Miniature, Black, TH"
U1: "42V Wide VIN 4-Switch Synchronous Buck-Boost Controller, PWP0028F"
ZZ2 ZZ3 ZZ4 ZZ5 ZZ6 ZZ7 ZZ8: library part AssemblyNote

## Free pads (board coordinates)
  rect 2x4.1 smd: 0(79.502,15.24) 0(85.344,71.374) 1(79.502,6.604) 1(85.344,62.738)

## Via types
v1: diameter 0.8, hole 0.4, Top Layer to Bottom Layer, tented both sides, 696 vias
v2: diameter 0.8, hole 0.4, Top Layer to Bottom Layer, 220 vias
v3: diameter 0.7, hole 0.3, Top Layer to Bottom Layer, 142 vias
v4: diameter 0.813, hole 0.4, Top Layer to Bottom Layer, 112 vias
v5: diameter 1, hole 0.5, Top Layer to Bottom Layer, tented both sides, 74 vias
v6: diameter 0.7, hole 0.3, Top Layer to Bottom Layer, tented both sides, 25 vias
v7: diameter 0.6, hole 0.3, Top Layer to Bottom Layer, 15 vias
v8: diameter 0.7, hole 0.3, Top Layer to Bottom Layer, tented bottom, 5 vias
v9: diameter 0.6, hole 0.3, Top Layer to Bottom Layer, tented bottom, 3 vias
v10: diameter 0.965, hole 0.5, Top Layer to Bottom Layer, 2 vias
v11: diameter 0.65, hole 0.3, Top Layer to Bottom Layer, tented bottom, 2 vias
v12: diameter 0.67, hole 0.3, Top Layer to Bottom Layer, tented bottom, 1 vias
v13: diameter 0.9, hole 0.5, Top Layer to Bottom Layer, 1 vias

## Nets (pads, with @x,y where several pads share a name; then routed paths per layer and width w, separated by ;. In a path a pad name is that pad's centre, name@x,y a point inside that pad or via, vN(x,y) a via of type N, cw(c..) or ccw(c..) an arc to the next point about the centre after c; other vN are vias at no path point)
CS: D2.2 Q3.1 Q3.2 Q3.3 Q4.1 Q4.2 Q4.3 Q7.1 Q7.2 Q7.3 Q8.1 Q8.2 Q8.3 R6.1 R7.2 | length 15.7
  Top Layer w0.254: R7.2@42.473,45.72 v3(44.45,45.72)
  Bottom Layer w0.254: v3(44.45,45.72) 44.704,45.466 44.704,41.522 49.853,36.373 R6.1@51.943,36.373
  other v1: 37.465,44.45 37.465,45.72 37.465,46.99 37.465,48.26
  other v2: 40.132,27.305
  other v3: 41.529,33.147 41.529,34.163 42.672,34.417 43.561,34.925 39.37,36.195 41.148,40.767 43.942,40.767 41.148,42.037 43.942,42.037 41.148,43.307 43.942,43.307 41.148,44.577 43.942,44.577 41.148,45.847 41.148,46.99 43.942,46.99 43.942,48.26 41.148,49.53 43.942,49.53 41.148,50.8 43.942,50.8 41.148,52.197 42.545,52.197 43.942,52.197 41.148,53.594 42.545,53.594 41.529,54.737 43.688,55.626 42.418,56.769 43.688,56.896 42.418,58.039 43.688,62.992
  other v6: 39.37,32.131 40.513,32.512 39.37,33.02 40.513,33.401 40.64,36.83 39.37,37.465 40.64,38.1 39.37,38.735 39.37,51.435 40.259,52.07 39.37,52.705 40.259,53.34 39.37,53.975 39.37,57.785 40.513,57.785 39.37,59.055 40.513,59.055 39.37,60.325 40.513,60.325
CSG: C1.2 C2.2 C3.2 C4.2 C5.2 C6.2 C7.2 C8.2 C9.2 C10.2 C11.2 C12.2 C13.2 C14.2 C16.1 C17.2 C21.2 C23.2 C25.2 C26.2 C27.2 C28.2 C29.2 C30.2 C101.2 C102.2 C103.2 C104.2 C105.2 C106.2 C107.2 C108.2 C109.2 C110.2 C111.2 C112.2 J1.1 J2.1 J3.1 pad.1 R7.1 R8.1 R18.1 R19.1 R20.1 R22.1 R23.1 T2.1 T4.1 TP2.1 TP4.1 TP104.1 TP106.1 U1.10 U1.22 U1.29 | length 60.6
  Top Layer w0.254: v3@45.495,45.72 R7.1@47.073,45.72
  Bottom Layer w0.254: v3(45.466,45.749) 45.158,45.441 45.158,41.71 49.932,36.936 51.426,36.936 ; 53.319,36.936 52.46,36.936 ; 51.427,36.935 52.459,36.935 ; 51.426,36.936 51.427,36.935 ; 52.459,36.935 52.46,36.936
  Bottom Layer w0.305: 53.554,45.807 U1.22@55.189,45.807 U1.29@57.714,45.807 ; U1.29@59.182,43.857 U1.10@60.889,43.857 62.103,43.857
  Bottom Layer w0.35: 52.792,45.807 53.554,45.807
  Bottom Layer w0.406: 52.197,45.212 52.792,45.807 ; 62.103,43.857 69.114,43.857 69.215,43.958
  Bottom Layer w0.508: 74.549,40.005 75.58,38.974 75.58,38.847 77.216,37.211 J1.1@82.55,37.211
  Bottom Layer w0.61: C16.1@50.165,45.212 52.197,45.212 ; 74.422,49.784 77.19,49.784 80.365,46.609 J3.1@82.55,46.609 ; 74.422,52.705 74.542,52.585 82.049,52.585 J2.1@82.423,52.959
  other v1: 64.135,1.905 66.04,1.905 67.31,1.905 68.58,1.905 69.85,1.905 71.12,1.905 72.39,1.905 73.66,1.905 74.93,1.905 76.2,1.905 77.47,1.905 78.74,1.905 80.01,1.905 81.28,1.905 82.55,1.905 83.82,1.905 85.09,1.905 86.36,1.905 87.63,1.905 88.9,1.905 90.17,1.905 91.44,1.905 92.71,1.905 93.98,1.905 95.25,1.905 64.135,3.175 66.04,3.175 67.31,3.175 68.58,3.175 69.85,3.175 71.12,3.175 72.39,3.175 73.66,3.175 74.93,3.175 76.2,3.175 77.47,3.175 78.74,3.175 80.01,3.175 81.28,3.175 82.55,3.175 83.82,3.175 85.09,3.175 86.36,3.175 87.63,3.175 88.9,3.175 90.17,3.175 91.44,3.175 92.71,3.175 93.98,3.175 95.25,3.175 64.135,4.445 65.405,4.445 69.215,4.445 70.485,4.445 74.93,4.445 76.2,4.445 81.28,4.445 82.55,4.445 64.135,5.715 65.405,5.715 69.215,5.715 70.485,5.715 74.93,5.715 76.2,5.715 81.28,5.715 82.55,5.715 64.135,6.985 65.405,6.985 69.215,6.985 70.485,6.985 74.93,6.985 76.2,6.985 81.28,6.985 82.55,6.985 64.135,8.255 65.405,8.255 69.215,8.255 70.485,8.255 74.93,8.255 76.2,8.255 81.28,8.255 82.55,8.255 91.948,29.21 93.218,29.21 94.488,29.21 95.758,29.21 97.028,29.21 98.298,29.21 99.568,29.21 100.838,29.21 102.108,29.21 103.378,29.21 104.648,29.21 105.918,29.21 91.948,30.48 91.948,31.75 91.948,39.37 91.948,40.64 91.948,41.91 93.218,41.91 94.488,41.91 95.758,41.91 97.028,41.91 98.298,41.91 99.568,41.91 100.838,41.91 102.108,41.91 103.378,41.91 104.648,41.91 105.918,41.91 91.948,50.8 93.218,50.8 94.488,50.8 95.758,50.8 97.028,50.8 98.298,50.8 99.568,50.8 100.838,50.8 102.108,50.8 103.378,50.8 104.648,50.8 105.918,50.8 91.948,52.07 91.948,53.34 91.948,60.96 57.404,62.23 58.674,62.23 59.944,62.23 91.948,62.23 57.404,63.5 58.674,63.5 59.944,63.5 91.948,63.5 93.218,63.5 94.488,63.5 95.758,63.5 97.028,63.5 98.298,63.5 99.568,63.5 100.838,63.5 102.108,63.5 103.378,63.5 104.648,63.5 105.918,63.5 70.485,84.455 71.755,84.455 76.835,84.455 78.105,84.455 81.915,84.455 83.185,84.455 86.995,84.455 88.265,84.455 70.485,85.725 71.755,85.725 76.835,85.725 78.105,85.725 81.915,85.725 83.185,85.725 86.995,85.725 88.265,85.725 70.485,86.995 71.755,86.995 76.835,86.995 78.105,86.995 81.915,86.995 83.185,86.995 86.995,86.995 88.265,86.995 70.485,88.265 71.755,88.265 76.835,88.265 78.105,88.265 81.915,88.265 83.185,88.265 86.995,88.265 88.265,88.265 70.485,89.535 71.755,89.535 73.025,89.535 74.295,89.535 75.565,89.535 76.835,89.535 78.105,89.535 79.375,89.535 80.645,89.535 81.915,89.535 83.185,89.535 84.455,89.535 85.725,89.535 86.995,89.535 88.265,89.535 70.485,90.805 71.755,90.805 73.025,90.805 74.295,90.805 75.565,90.805 76.835,90.805 78.105,90.805 79.375,90.805 80.645,90.805 81.915,90.805 83.185,90.805 84.455,90.805 85.725,90.805 86.995,90.805 88.265,90.805
  other v2: 42.545,29.591 43.815,29.591 45.085,29.591 46.355,29.591 47.625,29.591 48.895,29.591 50.165,29.591 51.435,29.591 52.705,29.591 53.975,29.591 55.245,29.591 43.815,30.861 45.085,30.861 46.355,30.861 47.625,30.861 48.895,30.861 50.165,30.861 51.435,30.861 52.705,30.861 53.975,30.861 55.245,30.861 89.408,33.02 90.678,33.02 91.948,33.02 89.408,34.29 90.678,34.29 91.948,34.29 89.408,35.56 90.678,35.56 91.948,35.56 89.408,36.83 90.678,36.83 91.948,36.83 89.408,38.1 90.678,38.1 91.948,38.1 89.408,54.61 90.678,54.61 91.948,54.61 89.408,55.88 90.678,55.88 91.948,55.88 89.408,57.15 90.678,57.15 91.948,57.15 89.408,58.42 90.678,58.42 91.948,58.42 89.408,59.69 90.678,59.69 91.948,59.69 45.847,62.23 47.244,62.23 48.514,62.23 49.784,62.23 51.054,62.23 52.324,62.23 53.594,62.23 54.864,62.23 56.134,62.23 45.847,63.5 47.244,63.5 48.514,63.5 49.784,63.5 51.054,63.5 52.324,63.5 53.594,63.5 54.864,63.5 56.134,63.5
  other v3: 69.342,34.036 70.612,34.036 72.009,34.036 73.406,34.036 75.819,34.036 47.625,36.83 49.734,38.558 45.847,42.037 45.847,43.307 45.847,44.45 45.847,46.99 45.847,48.26 45.847,49.53 45.847,50.8 48.768,50.927 47.752,52.07 46.736,52.705 45.847,53.721 65.786,56.261 73.025,59.69 74.295,59.69 75.565,59.69
  other v4: 93.726,31.496 94.869,31.496 102.997,31.496 104.14,31.496 105.283,31.496 106.426,31.496 93.726,32.639 104.14,32.639 105.283,32.639 106.426,32.639 105.283,33.782 106.426,33.782 105.283,34.925 106.426,34.925 105.283,36.068 106.426,36.068 105.283,37.211 106.426,37.211 93.726,38.354 104.14,38.354 105.283,38.354 106.426,38.354 93.726,39.497 94.869,39.497 102.997,39.497 104.14,39.497 105.283,39.497 106.426,39.497 93.726,53.086 94.869,53.086 102.997,53.086 104.14,53.086 105.283,53.086 106.426,53.086 93.726,54.229 104.14,54.229 105.283,54.229 106.426,54.229 105.283,55.372 106.426,55.372 105.283,56.515 106.426,56.515 105.283,57.658 106.426,57.658 105.283,58.801 106.426,58.801 93.726,59.944 104.14,59.944 105.283,59.944 106.426,59.944 93.726,61.087 94.869,61.087 102.997,61.087 104.14,61.087 105.283,61.087 106.426,61.087
  other v7: 57.039,43.482 58.039,43.482 59.039,43.482 57.039,44.482 58.039,44.482 59.039,44.482 57.039,45.482 58.039,45.482 59.039,45.482 57.039,46.482 58.039,46.482 59.039,46.482 57.039,47.482 58.039,47.482 59.039,47.482
  other v12: 51.562,45.212
DITHER: C27.1 J3.2 U1.5 | length 26.7
  MidLayer4 w0.4: v3(66.802,51.141) 67.35,51.689 77.216,51.689 v3(78.613,50.292)
  Bottom Layer w0.254: U1.5@60.889,47.107 63.89,47.107 64.297,47.514 64.297,49.2 66.238,51.141 v3(66.802,51.141)
  Bottom Layer w0.35: v3(66.802,51.141) C27.1@67.936,51.141
  Bottom Layer w0.508: v3(78.613,50.292) 79.756,49.149 J3.2@82.55,49.149
EN: C23.1 J2.2 R13.1 R18.2 U1.1 | length 29.5
  MidLayer4 w0.5: v3(61.989,50.546) 63.894,52.451 65.008,52.451 v3(66.675,52.451) 75.057,52.451 v3(76.327,53.721)
  Bottom Layer w0.254: U1.1@60.889,49.707 61.545,49.707 61.989,50.151 v3(61.989,50.546)
  Bottom Layer w0.35: R13.1@67.945,55.688 67.945,54.991 68.007,54.929 C23.1@68.007,53.721 R18.2@68.007,52.451
  Bottom Layer w0.4: v3(66.675,52.451) R18.2@68.007,52.451
  Bottom Layer w0.5: v3(76.327,53.721) 76.327,54.991 76.835,55.499 J2.2@82.423,55.499
HO1: R2.2 R3.2 U1.27 | length 31.6
  MidLayer4 w0.61: v2(31.242,63.676) 31.745,63.174 37.901,63.174 38.403,63.676 v2(40.132,63.676) 41.353,63.676 44.992,60.037 44.992,58.828 48.802,55.018 48.802,54.771 53.213,50.36 v8(53.213,49.276)
  Bottom Layer w0.305: v8@53.432,49.057 U1.27@55.189,49.057
HO2: R24.2 R25.2 U1.19 | length 30.5
  MidLayer4 w0.61: v2@38.989,30.038 v2(38.989,29.972) 41.646,29.972 43.678,32.004 49.657,32.004 50.673,33.02 50.673,39.169 50.453,39.389 50.453,41.248 51.05,41.845 51.05,42.099 51.243,42.099 v11(52.705,43.561)
  Bottom Layer w0.305: v11(52.705,43.561) 53.001,43.857 U1.19@55.189,43.857
  Bottom Layer w0.61: R25.2@37.648,27.33 37.657,27.339 R24.2@37.657,28.702 38.927,29.972 v2(38.989,29.972)
LO1: R4.2 R5.2 U1.25 | length 23.3
  MidLayer4 w0.61: v2(44.958,52.959) 50.038,47.879 v9(51.689,47.879)
  Bottom Layer w0.305: v9(51.689,47.879) 51.708,47.86 53.721,47.86 53.824,47.757 U1.25@55.189,47.757
  Bottom Layer w0.61: 40.887,56.707 41.21,56.707 41.465,56.451 ; R4.2@41.594,61.722 41.465,61.594 41.465,56.451 ; v2(44.958,52.959) 41.465,56.451
LO2: R26.2 R27.2 U1.21 | length 16.1
  MidLayer4 w0.61: v2@44.958,39.366 49.962,44.371 52.499,44.371 v9(53.213,45.085)
  Bottom Layer w0.305: v9@53.285,45.157 U1.21@55.189,45.157
  Bottom Layer w0.61: 43.499,36.569 R27.2@43.499,38.227 43.815,38.227 v2(44.958,39.37)
MODE: C26.1 J1.2 R19.2 U1.4 | length 32.9
  MidLayer4 w0.5: v11(62.611,47.768) 65.675,44.704 77.597,44.704 v3(78.994,46.101)
  Bottom Layer w0.254: U1.4@60.889,47.757 62.6,47.757 v11(62.611,47.768)
  Bottom Layer w0.35: R19.2@75.757,48.784 C26.1@75.757,47.514 77.581,47.514 v3(78.994,46.101)
  Bottom Layer w0.4: v3(78.994,46.101) 78.994,45.847 80.899,43.942 80.899,41.783 82.55,40.132 J1.2@82.55,39.751
NetC1_1: C1.1 C101.1 C108.1 C109.1 L101.1 pad.0@85.344,71.374 T1.1 TP1.1
  other v1: 70.485,68.58 71.755,68.58 76.835,68.58 93.218,68.58 94.488,68.58 95.758,68.58 97.028,68.58 98.298,68.58 99.568,68.58 100.838,68.58 102.108,68.58 103.378,68.58 104.648,68.58 105.918,68.58 91.948,69.342 70.485,69.85 71.755,69.85 76.835,69.85 91.948,70.612 70.485,71.12 71.755,71.12 76.835,71.12 70.485,72.39 71.755,72.39 76.835,72.39 64.135,73.66 65.405,73.66 67.945,73.66 69.215,73.66 70.485,73.66 71.755,73.66 76.835,73.66 78.105,73.66 79.375,73.66 80.645,73.66 81.915,73.66 83.185,73.66 84.455,73.66 85.725,73.66 73.025,74.295 74.295,74.295 75.565,74.295 64.135,74.93 70.485,74.93 71.755,74.93 76.835,74.93 78.105,74.93 79.375,74.93 80.645,74.93 81.915,74.93 83.185,74.93 86.995,74.93 64.135,76.2 70.485,76.2 71.755,76.2 76.835,76.2 78.105,76.2 79.375,76.2 80.645,76.2 81.915,76.2 83.185,76.2 86.995,76.2 64.135,77.47 70.485,77.47 71.755,77.47 76.835,77.47 78.105,77.47 81.915,77.47 83.185,77.47 86.995,77.47 88.265,77.47 91.948,78.232 64.135,78.74 65.405,78.74 67.945,78.74 69.215,78.74 70.485,78.74 71.755,78.74 76.835,78.74 78.105,78.74 81.915,78.74 83.185,78.74 86.995,78.74 88.265,78.74 91.948,79.502 70.485,80.01 71.755,80.01 76.835,80.01 78.105,80.01 81.915,80.01 83.185,80.01 86.995,80.01 88.265,80.01 93.218,80.264 94.488,80.264 95.758,80.264 97.028,80.264 98.298,80.264 99.568,80.264 100.838,80.264 102.108,80.264 103.378,80.264 104.648,80.264 105.918,80.264 70.485,81.28 71.755,81.28 76.835,81.28 78.105,81.28 81.915,81.28 83.185,81.28 86.995,81.28 88.265,81.28
  other v2: 89.408,71.882 90.678,71.882 91.948,71.882 89.408,73.152 90.678,73.152 91.948,73.152 89.408,74.422 90.678,74.422 91.948,74.422 69.215,74.93 89.408,75.692 90.678,75.692 91.948,75.692 69.215,76.2 89.408,76.962 90.678,76.962 91.948,76.962 69.215,77.47
  other v4: 93.599,70.358 94.742,70.358 102.87,70.358 104.013,70.358 105.156,70.358 106.299,70.358 93.599,71.501 104.013,71.501 105.156,71.501 106.299,71.501 105.156,72.644 106.299,72.644 105.156,73.787 106.299,73.787 105.156,74.93 106.299,74.93 105.156,76.073 106.299,76.073 93.599,77.216 104.013,77.216 105.156,77.216 106.299,77.216 93.599,78.359 94.742,78.359 102.87,78.359 104.013,78.359 105.156,78.359 106.299,78.359
NetC15_1: C15.1 R6.2 U1.16 | length 5.3
  Bottom Layer w0.305: 52.386,39.998 52.386,40.201 54.092,41.907 U1.16@55.189,41.907
  Bottom Layer w0.4: 51.943,38.1 51.932,38.111 51.932,39.043 C15.1@52.386,39.497
NetC15_2: C15.2 R8.2 U1.15 | length 3.6
  Bottom Layer w0.305: 53.786,39.998 53.786,40.586 54.457,41.257 U1.15@55.189,41.257
  Bottom Layer w0.4: R8.2@53.721,38.176 53.786,38.241 C15.2@53.786,39.497
NetC17_1: C17.1 R9.1 U1.2 | length 6.8
  Bottom Layer w0.305: U1.2@60.889,49.057 61.884,49.057 62.865,50.038 62.865,51.578 62.611,51.832 C17.1@61.341,51.832 ; C17.1@61.341,51.894 R9.1@61.341,53.164
NetC18_2: C18.2 D4.1 U1.26 | length 7.9
  Bottom Layer w0.305: D4.1@47.625,49.233 49.446,49.233 49.722,48.957 C18.2@50.673,48.957 52.516,48.957 53.108,48.365 55.147,48.365 U1.26@55.189,48.407
NetC19_1: C19.1 D5.1 U1.20 | length 8.1
  Bottom Layer w0.305: D5.1@47.625,43.223 49.446,43.223 49.722,43.499 C19.1@50.546,43.499 51.627,43.499 52.556,44.428 53.699,44.428 53.778,44.507 U1.20@55.189,44.507
NetC20_1: C20.1 R20.2 U1.6 | length 21.5
  MidLayer4 w0.5: v3(66.238,49.871) 66.763,49.346 72.701,49.346 v3(75.692,46.355)
  Bottom Layer w0.254: U1.6@60.889,46.457 64.247,46.457 64.751,46.961 64.751,48.384 v3(66.238,49.871)
  Bottom Layer w0.35: v3(66.238,49.871) R20.2@67.936,49.871 ; C20.1@75.692,45.023 v3(75.692,46.355)
NetC20_2: C20.2 TP7.1 | length 6.1
  Bottom Layer w0.35: C20.2@75.692,43.623 75.692,40.64 TP7.1@77.923,38.409
NetC21_1: C21.1 U1.8 | length 8.7
  Bottom Layer w0.254: U1.8@60.889,45.157 65.08,45.157 65.659,45.736 65.659,47.006 65.913,47.26 C21.1@68.007,47.26
NetC22_1: C22.1 C28.1 U1.9 | length 7.2
  Bottom Layer w0.254: U1.9@60.889,44.507 65.7,44.507 65.975,44.782 C22.1@66.675,44.782
  Bottom Layer w0.35: C22.1@66.675,44.782 C28.1@67.945,44.782
NetC22_2: C22.2 R23.2 | length 1.1
  Bottom Layer w0.35: C22.2@66.867,45.99 R23.2@68.007,45.99
NetC24_1: C24.1 R21.2 U1.14 | length 4
  Bottom Layer w0.254: U1.14@60.889,41.257 62.248,41.257 62.8,40.705 C24.1@62.8,39.878
  Bottom Layer w0.35: R21.2@62.8,38.862 C24.1@62.8,39.878
NetC24_2: C24.2 R16.2 U1.13 | length 6.1
  Bottom Layer w0.254: U1.13@60.889,41.907 63.63,41.907 64.2,41.337 C24.2@64.2,39.878
  Bottom Layer w0.35: R16.2@64.2,38.735 C24.2@64.2,39.878
NetC25_1: C25.1 R12.1 TP6.1 U1.24 | length 35.7
  Top Layer w0.305: v9@53.23,47.134 C25.1@54.829,47.134
  MidLayer4 w0.4: TP6.1@58.039,53.086 58.039,51.943 v9(53.213,47.117) 53.213,46.082 53.918,45.377 53.918,44.088 53.786,43.956 53.786,39.984 54.654,39.116 65.913,39.116 v8(66.294,39.497)
  Bottom Layer w0.305: v9@53.223,47.107 U1.24@55.189,47.107 ; R12.1@66.229,35.814 66.229,39.432 v8(66.294,39.497)
NetC29_1: C29.1 U1.7 | length 8.9
  Bottom Layer w0.254: U1.7@60.889,45.807 64.714,45.807 65.205,46.298 65.205,47.568 66.238,48.601 C29.1@67.936,48.601
NetC30_1: C30.1 R17.2 U1.12 | length 9.4
  Bottom Layer w0.254: U1.12@60.889,42.557 64.123,42.557 66.294,40.386 C30.1@68.007,40.386
  Bottom Layer w0.35: R17.2@67.945,38.927 C30.1@67.945,40.324
NetD3_1: D3.1 R9.2 | length 3.4
  Bottom Layer w0.305: R9.2@61.341,54.564 D3.1@61.341,57.955
NetQ1_4: Q1.4 R2.1 | length 2.7
  Top Layer w0.61: Q1.4@37.592,65.501 39.732,65.501 v2(40.132,65.102)
NetQ2_4: Q2.4 R3.1 | length 3.1
  Top Layer w0.61: Q2.4@28.321,65.501 30.83,65.501 v2(31.242,65.089)
NetQ3_4: Q3.4 R4.1 | length 1.6
  Top Layer w0.61: 38.299,61.976 38.989,61.976 v2(39.243,61.722)
  Bottom Layer w0.61: v2(39.243,61.722) 39.751,61.722
NetQ4_4: Q4.4 R5.1 | length 2.2
  Top Layer w0.61: 38.299,55.245 39.116,55.245 v2(39.243,55.372)
  Bottom Layer w0.61: v2(39.243,55.372) 39.308,55.307 R5.1@40.386,55.307
NetQ5_4: Q5.4 R24.1 | length 5.5
  Top Layer w0.61: Q5.4@32.512,26.955 v2(32.512,28.702)
  Bottom Layer w0.61: v2(32.512,28.702) R24.1@36.257,28.702
NetQ6_4: Q6.4 R25.1 | length 15.2
  Top Layer w0.61: Q6.4@22.733,26.955 v3@22.733,28.194
  Bottom Layer w0.61: v3(22.733,28.321) 23.724,27.33 R25.1@36.248,27.33
NetQ7_4: Q7.4 R26.1 | length 5.3
  Top Layer w0.61: Q7.4@37.623,34.29 v2(39.37,34.29)
  Bottom Layer w0.61: v2@39.424,34.344 v2(39.37,34.29) 40.321,34.29 R26.1@42.099,36.068
NetQ8_4: Q8.4 R27.1 | length 6
  Top Layer w0.635: Q8.4@37.623,41.275 39.394,41.275 v2(39.402,41.283)
  Bottom Layer w0.635: v2(39.402,41.283) 40.132,40.553 40.132,40.194 R27.1@42.099,38.227
NetR10_1: R10.1 TP5.1 U1.17 | length 38.5
  MidLayer4 w0.305: TP5.1@79.121,43.18 TP5.1@79.124,43.18
  MidLayer4 w0.4: v8(51.308,40.894) 51.308,39.751 54.213,36.846 69.459,36.846 72.11,39.497 73.533,39.497 77.216,43.18 TP5.1@78.867,43.18
  Bottom Layer w0.305: v8@51.435,41.021 v8(51.308,40.894) 52.197,40.894 53.86,42.557 U1.17@55.189,42.557
  Bottom Layer w0.4: v8(54.864,36.83) 55.245,37.211 R10.1@55.245,37.908
NetR11_1: R11.1 R14.2 TP103.1 | length 8.9
  MidLayer4 w0.5: v3(68.961,41.656) 68.961,39.243 v10@69.469,38.735
  Bottom Layer w0.4: R14.2@68.01,41.656 v3(68.961,41.656) ; TP103.1@70.485,35.687 69.723,36.449 v10(69.723,38.481) R11.1@71.436,38.481
NetR14_1: R14.1 R22.2 U1.11 | length 7.1
  Bottom Layer w0.254: U1.11@60.889,43.207 65.648,43.207 65.913,42.942 66.609,42.942 R22.2@66.61,42.942
  Bottom Layer w0.4: R14.1@66.61,41.656 R22.2@66.61,42.942
NetR15_1: R15.1 U1.3 | length 12.2
  Bottom Layer w0.254: U1.3@60.889,48.407 62.123,48.407 63.754,50.038 R15.1@63.754,58.736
